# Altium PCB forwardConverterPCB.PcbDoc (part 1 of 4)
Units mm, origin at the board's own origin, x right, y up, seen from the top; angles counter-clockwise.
Board outline 382.81 x 370.12 mm, 8 copper layers (L1, L2 (GND), L3, L4, L5(GND), L6, L7 (GND), L8), stack 1.028 mm thick; 352 components, 187 nets, 1188 pads, 1016 vias.
Unrouted connection lines stored in the file: 19.
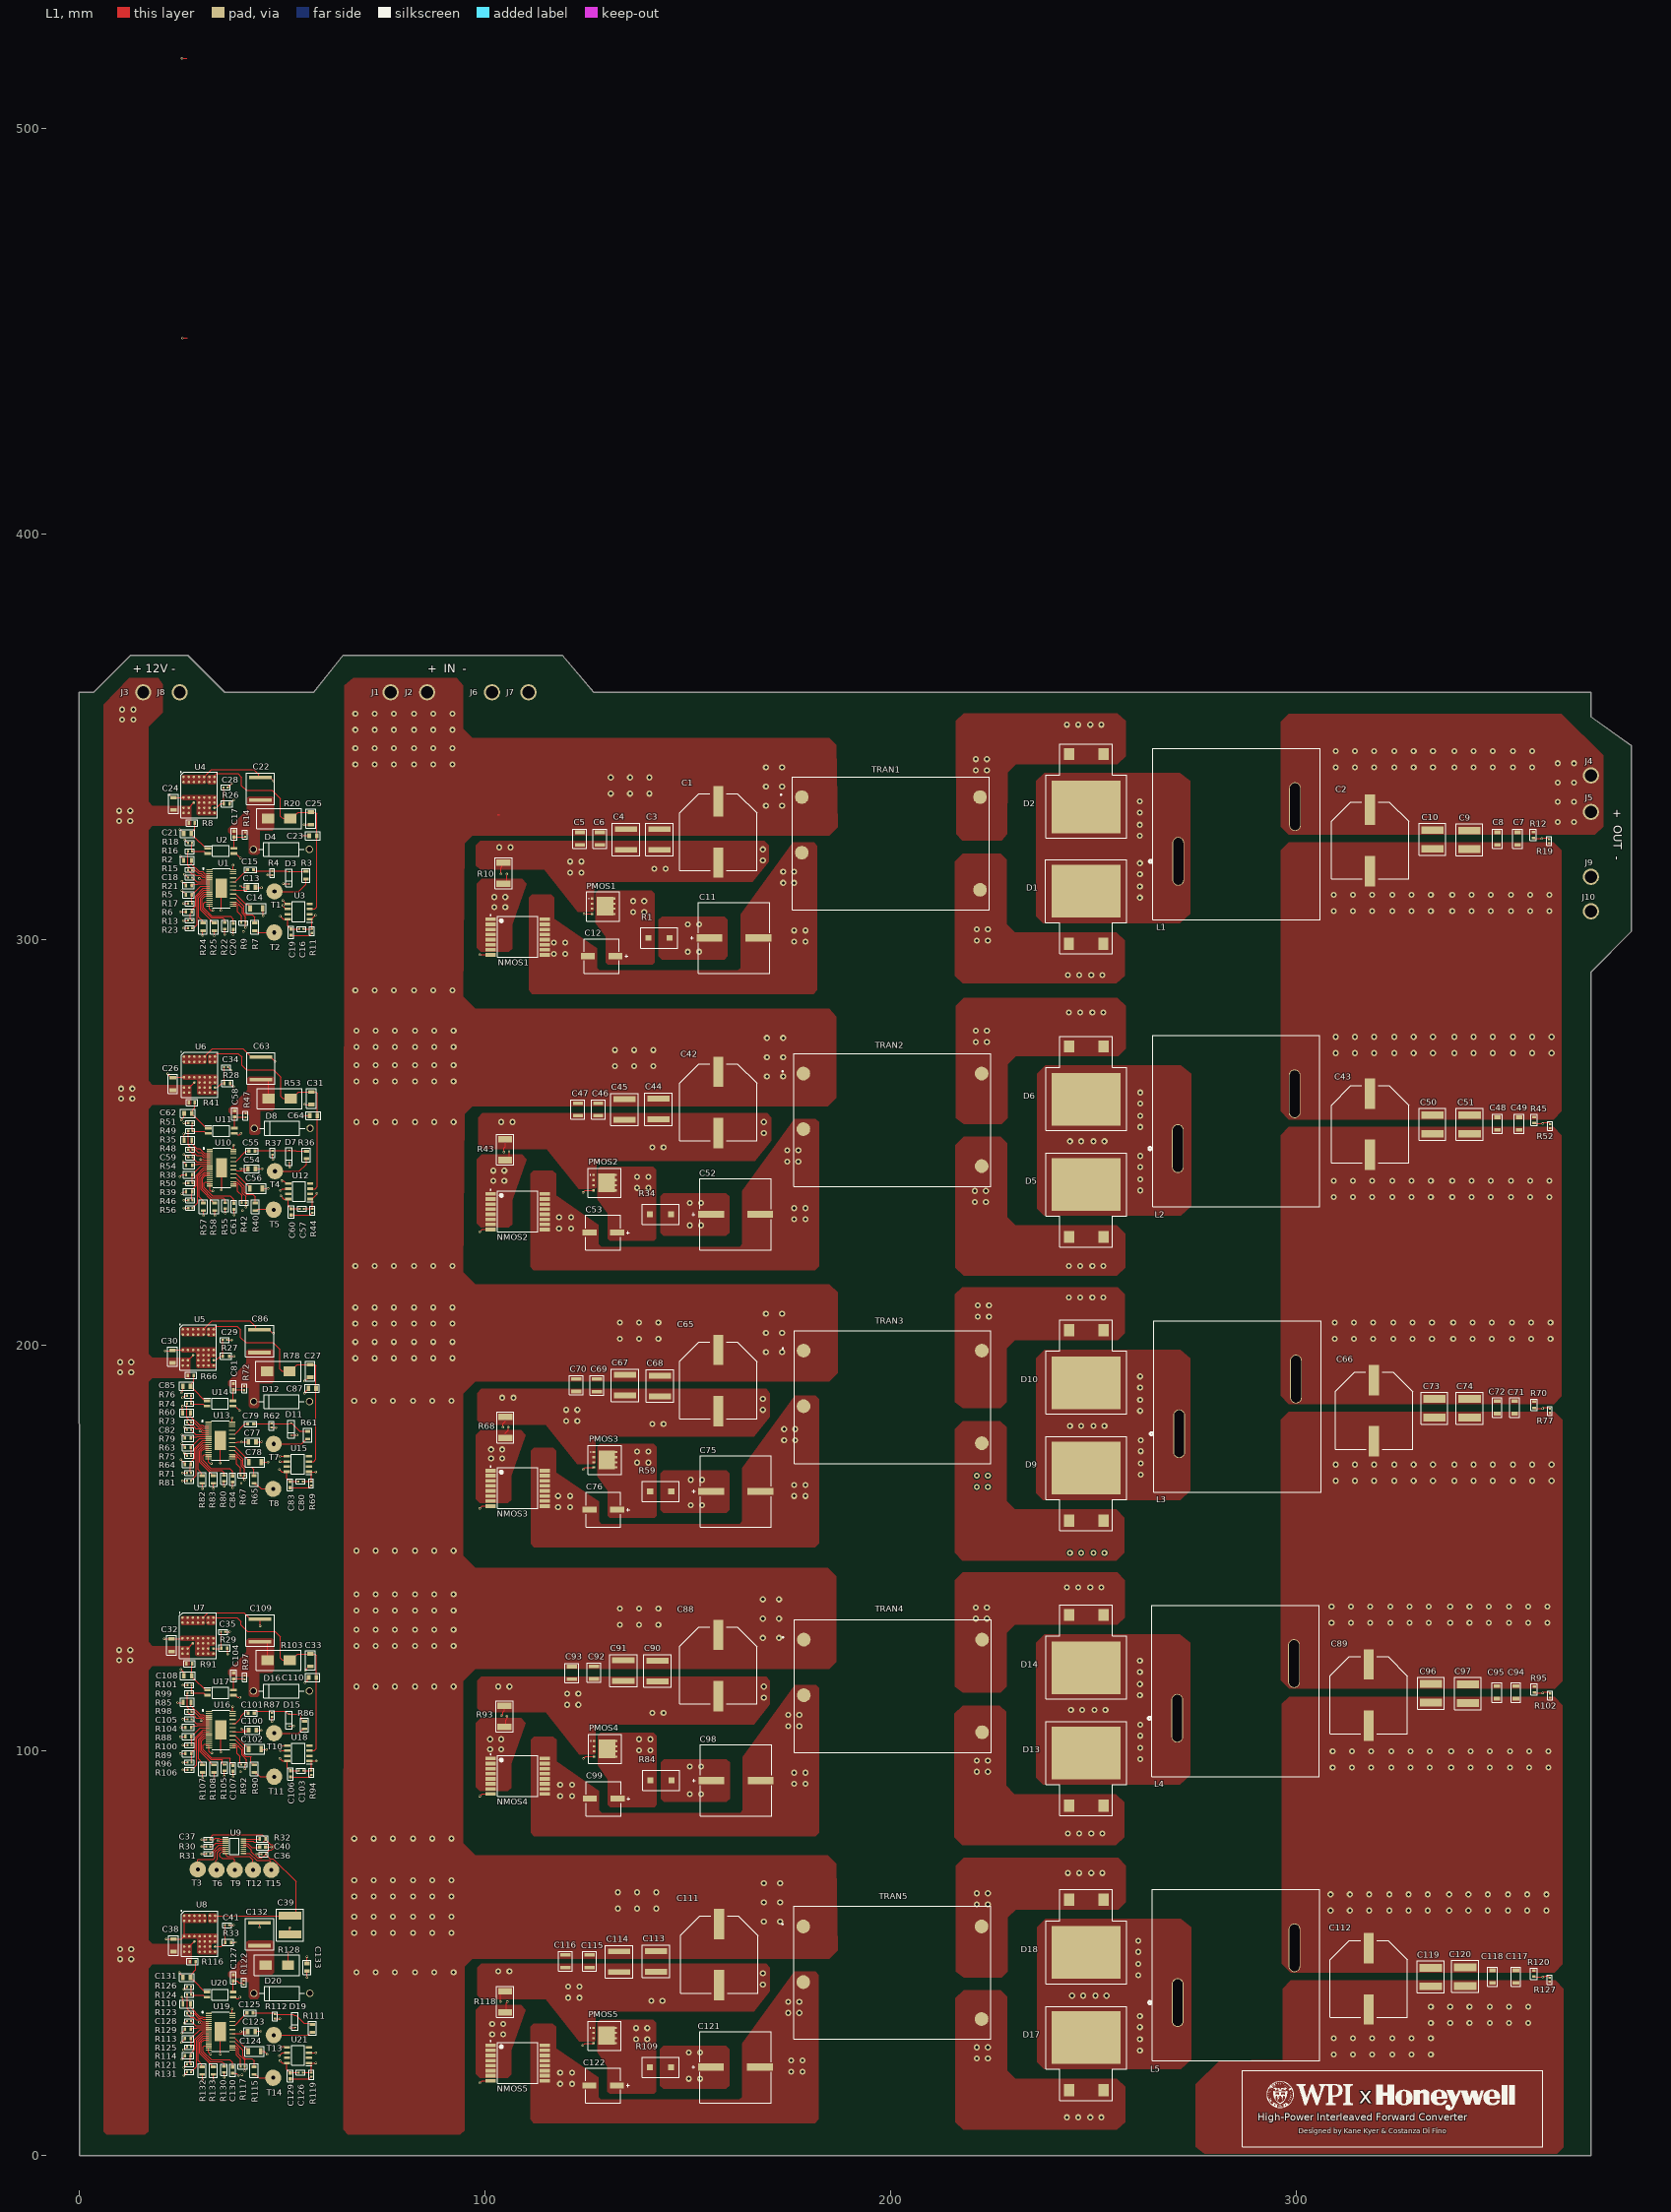
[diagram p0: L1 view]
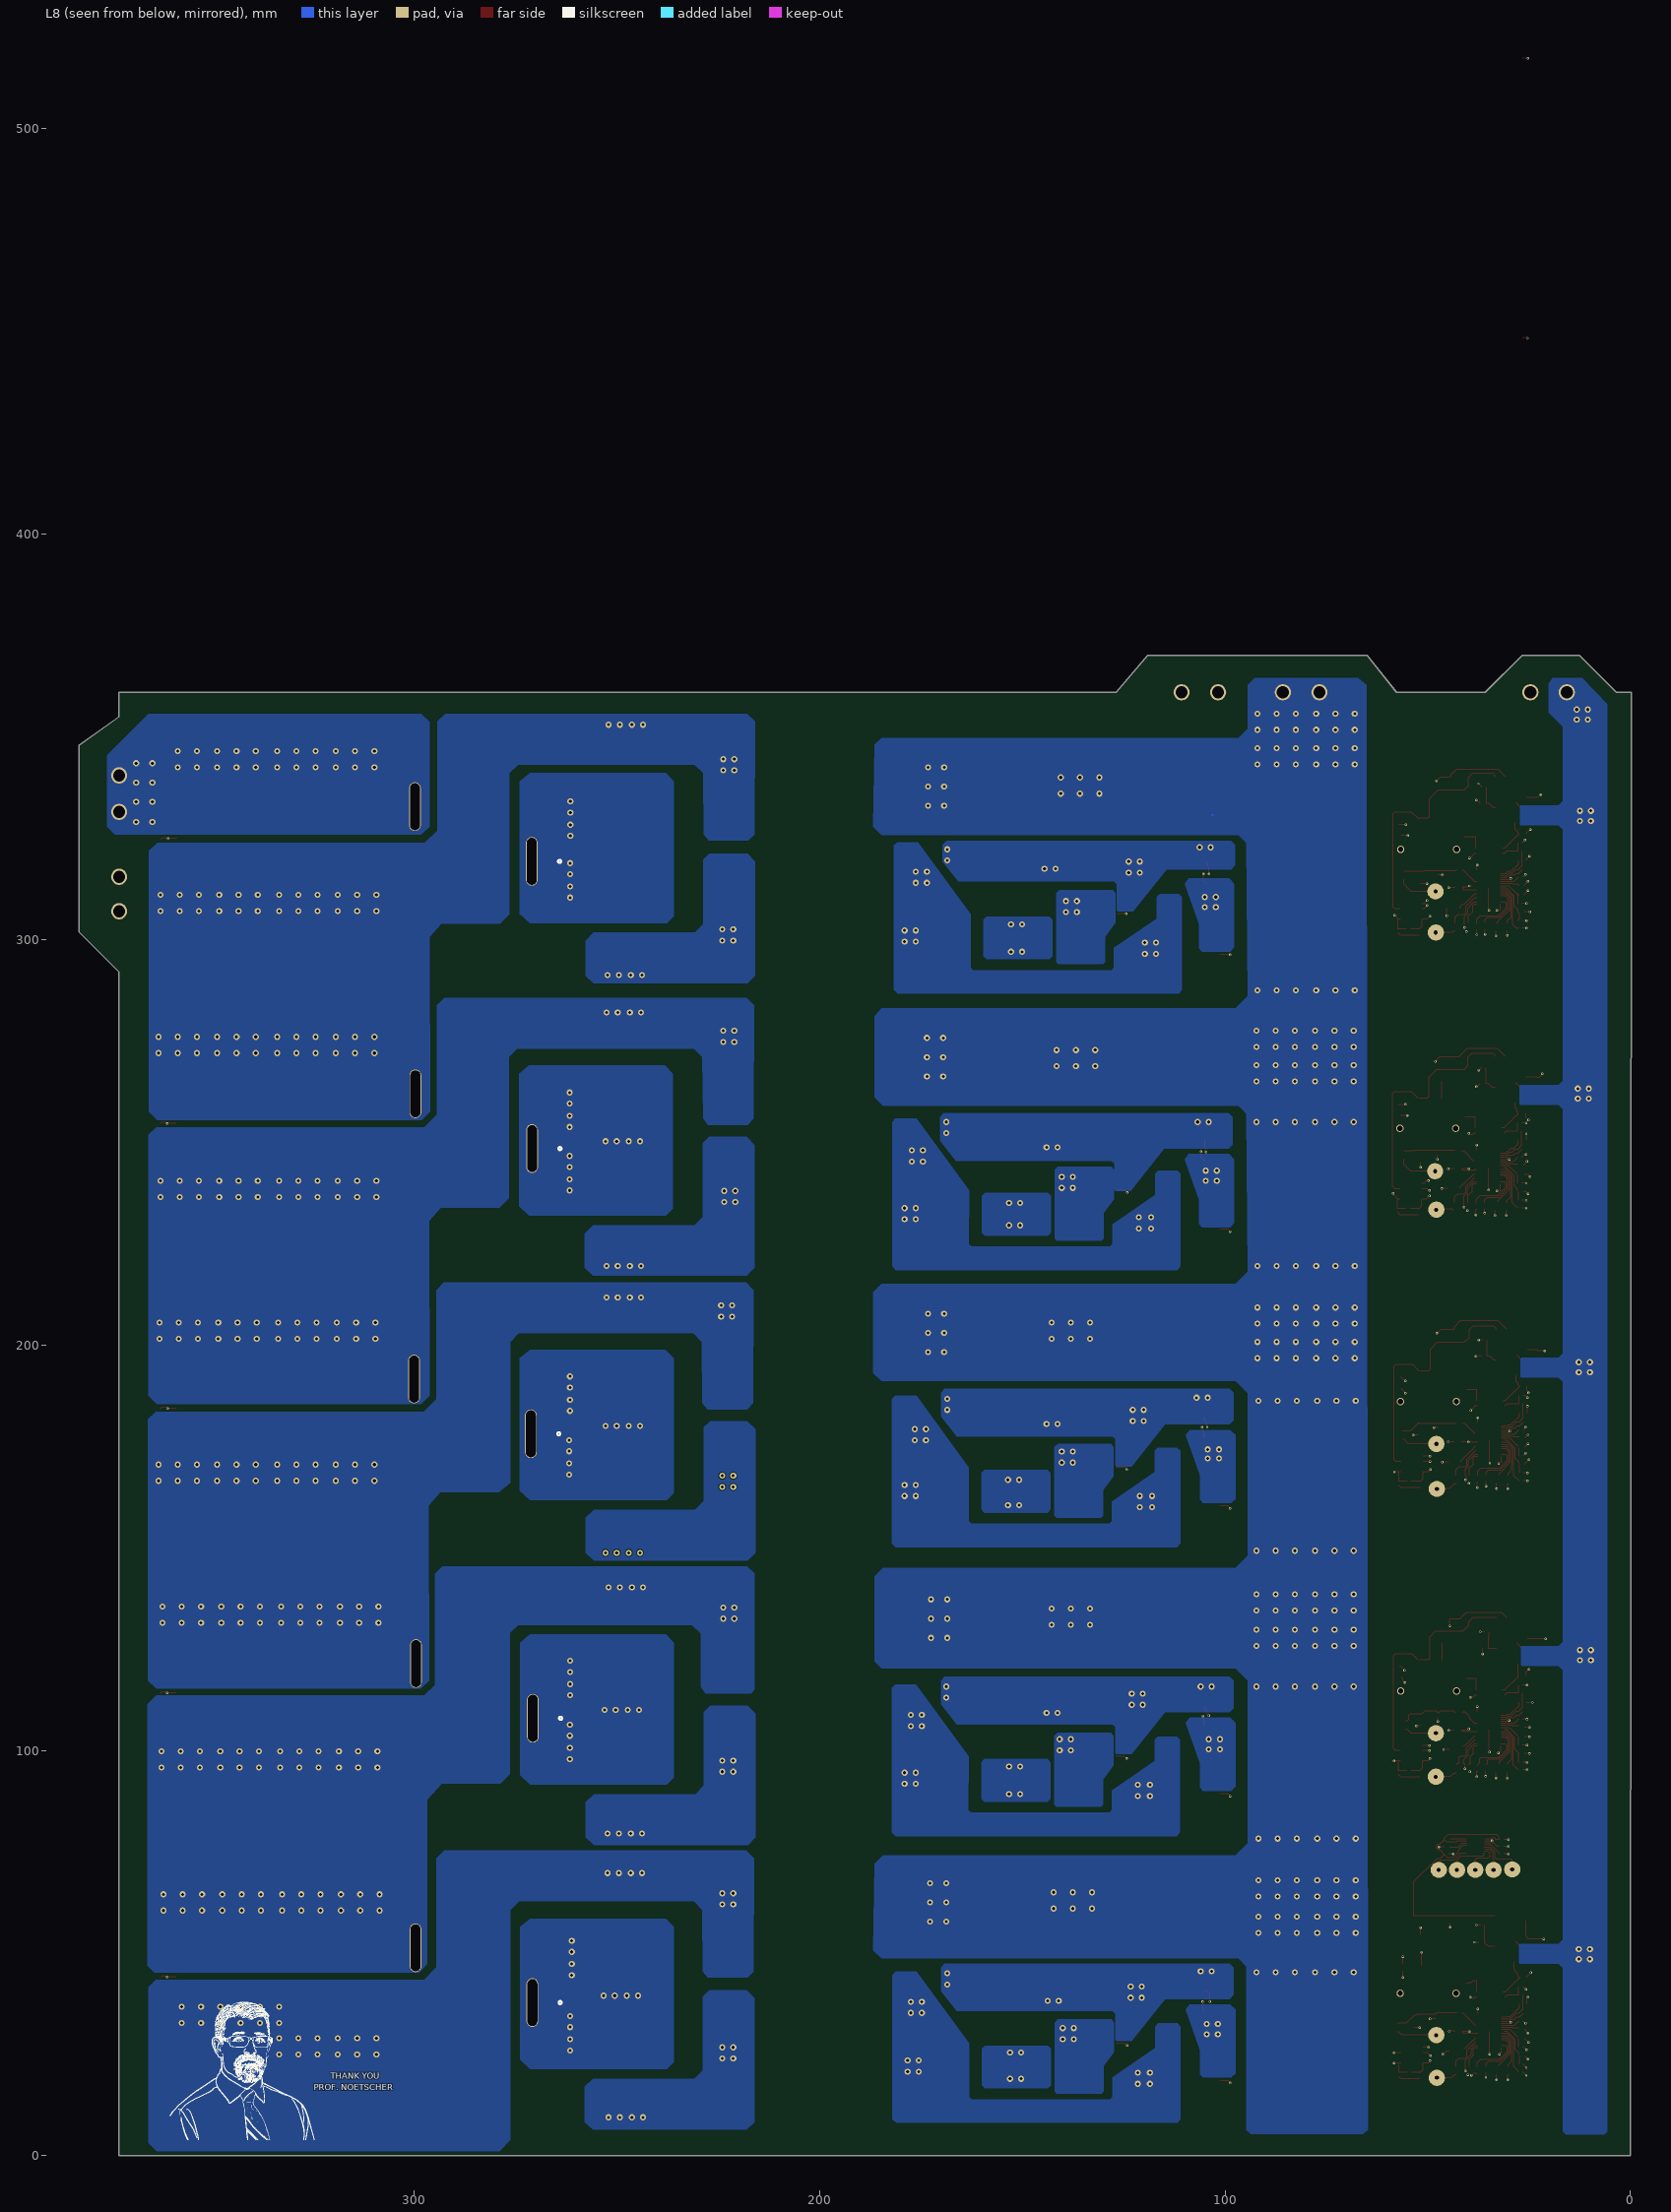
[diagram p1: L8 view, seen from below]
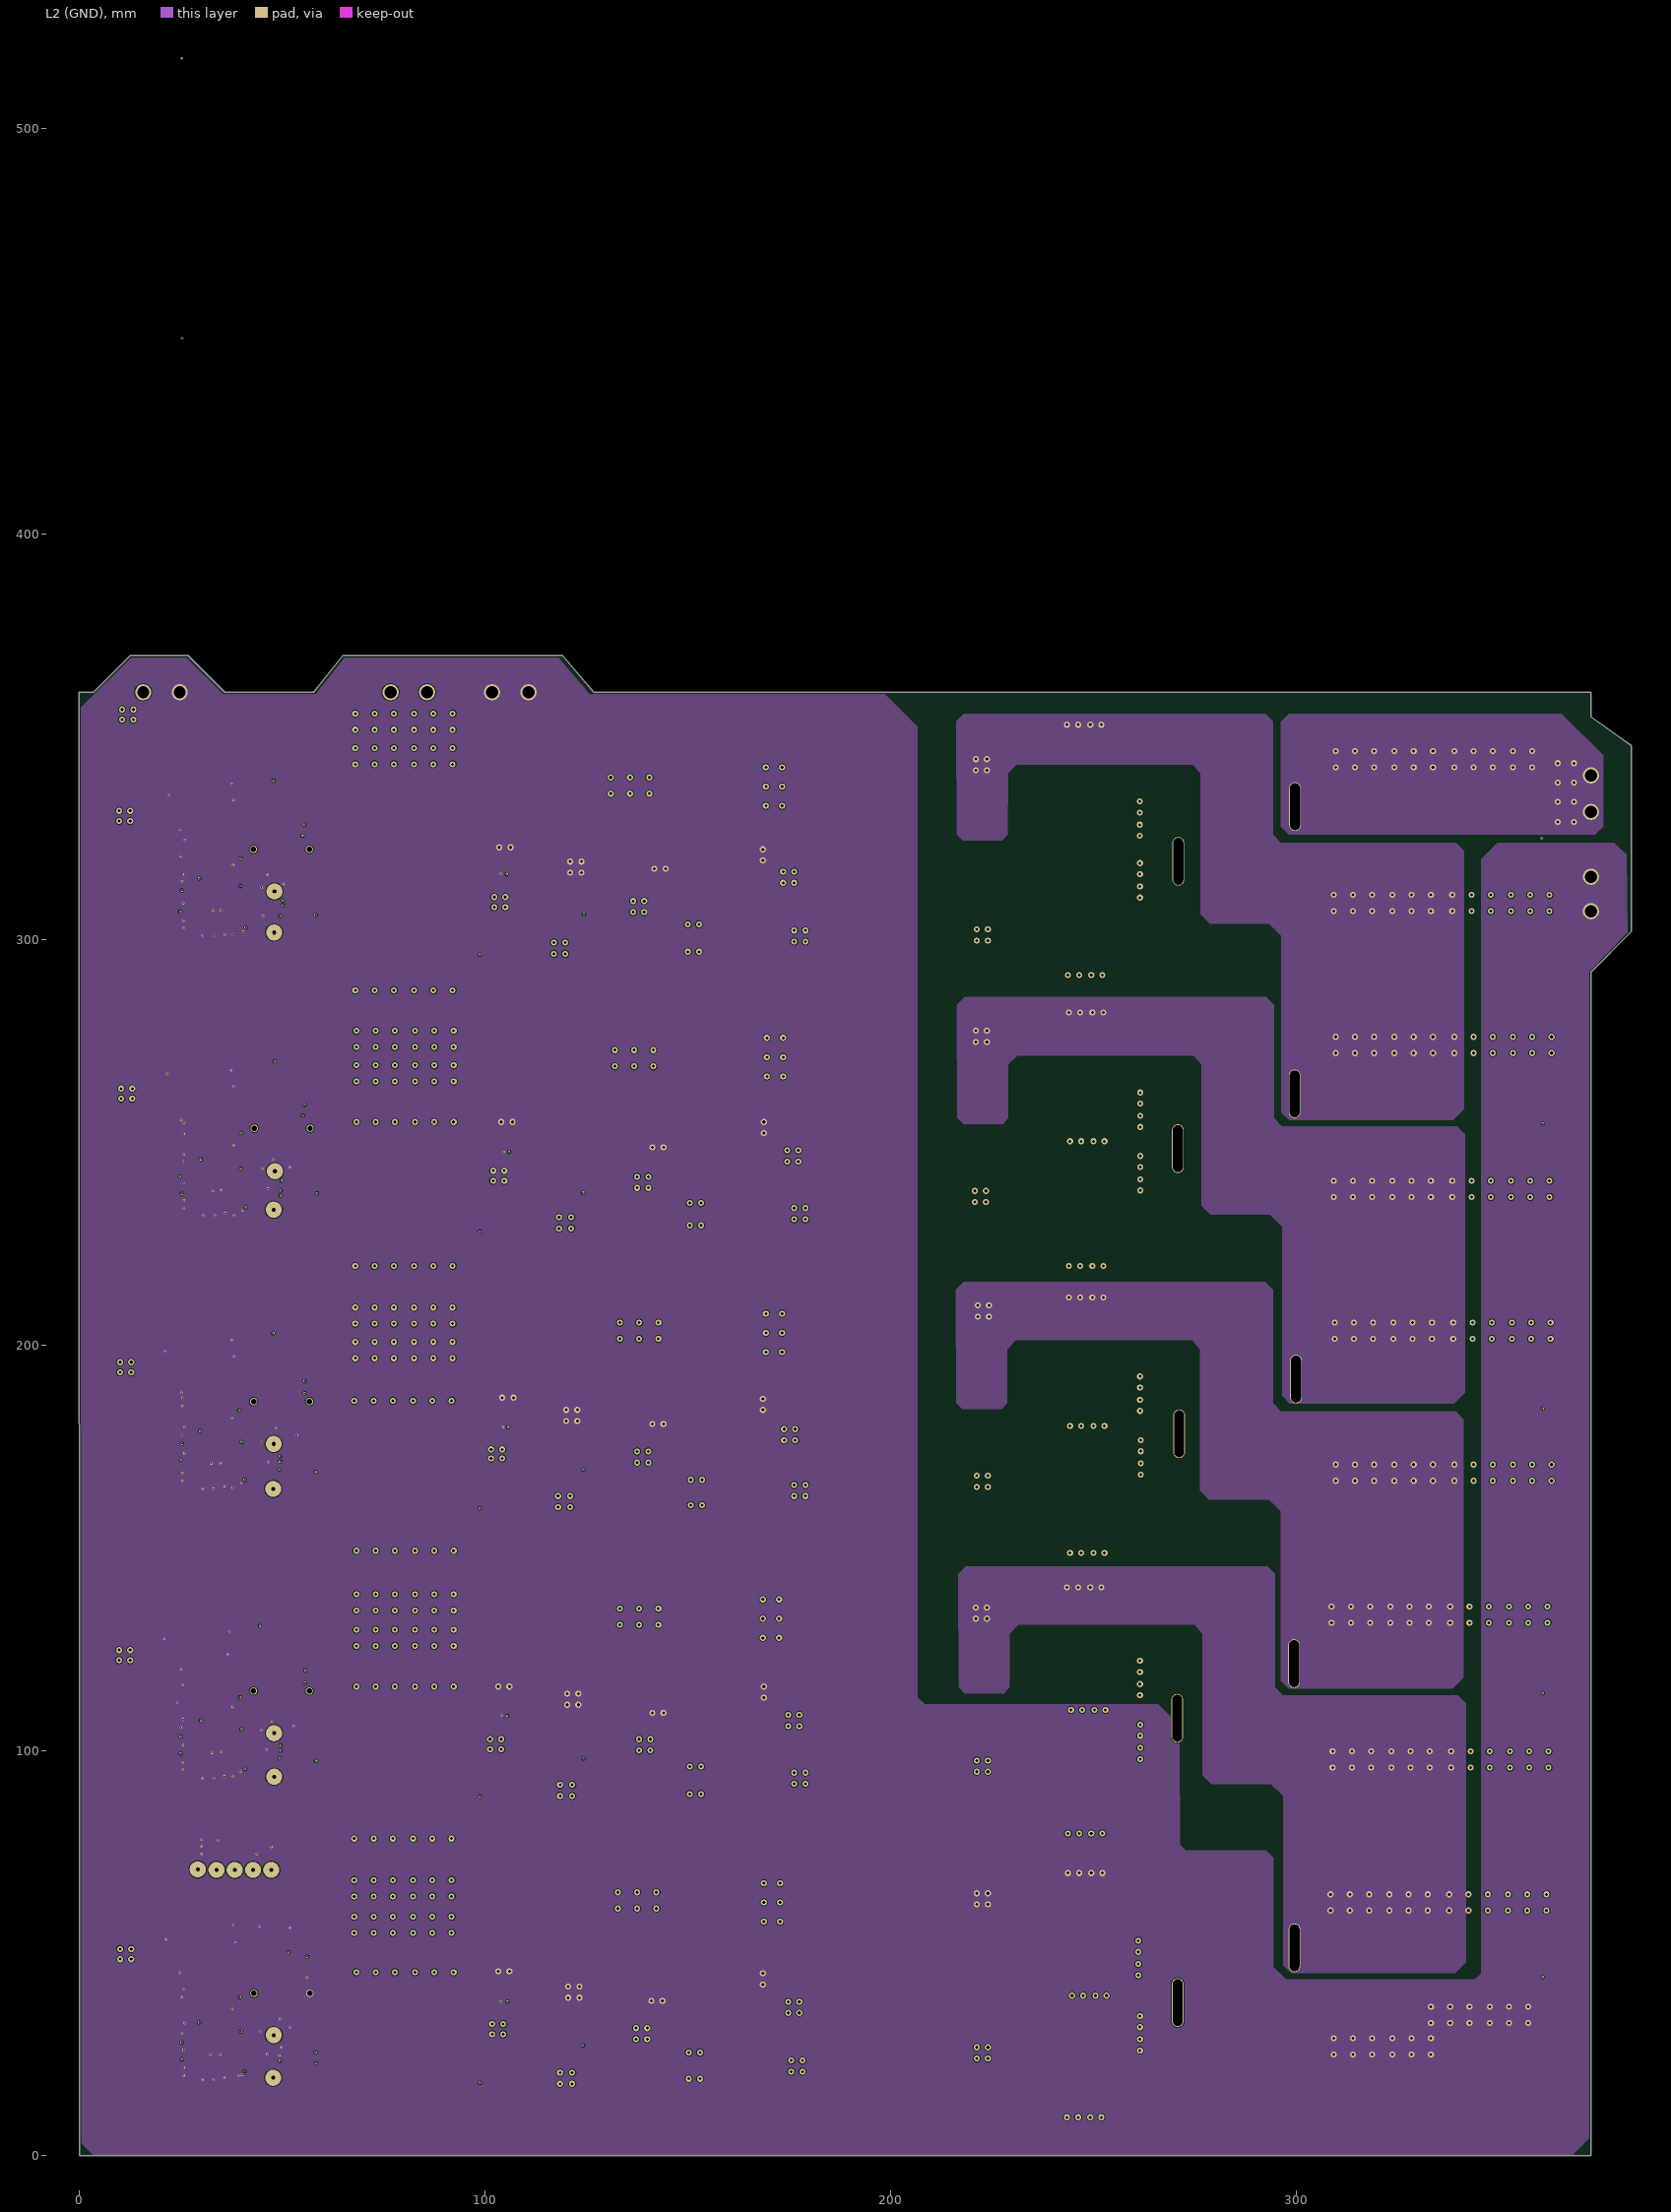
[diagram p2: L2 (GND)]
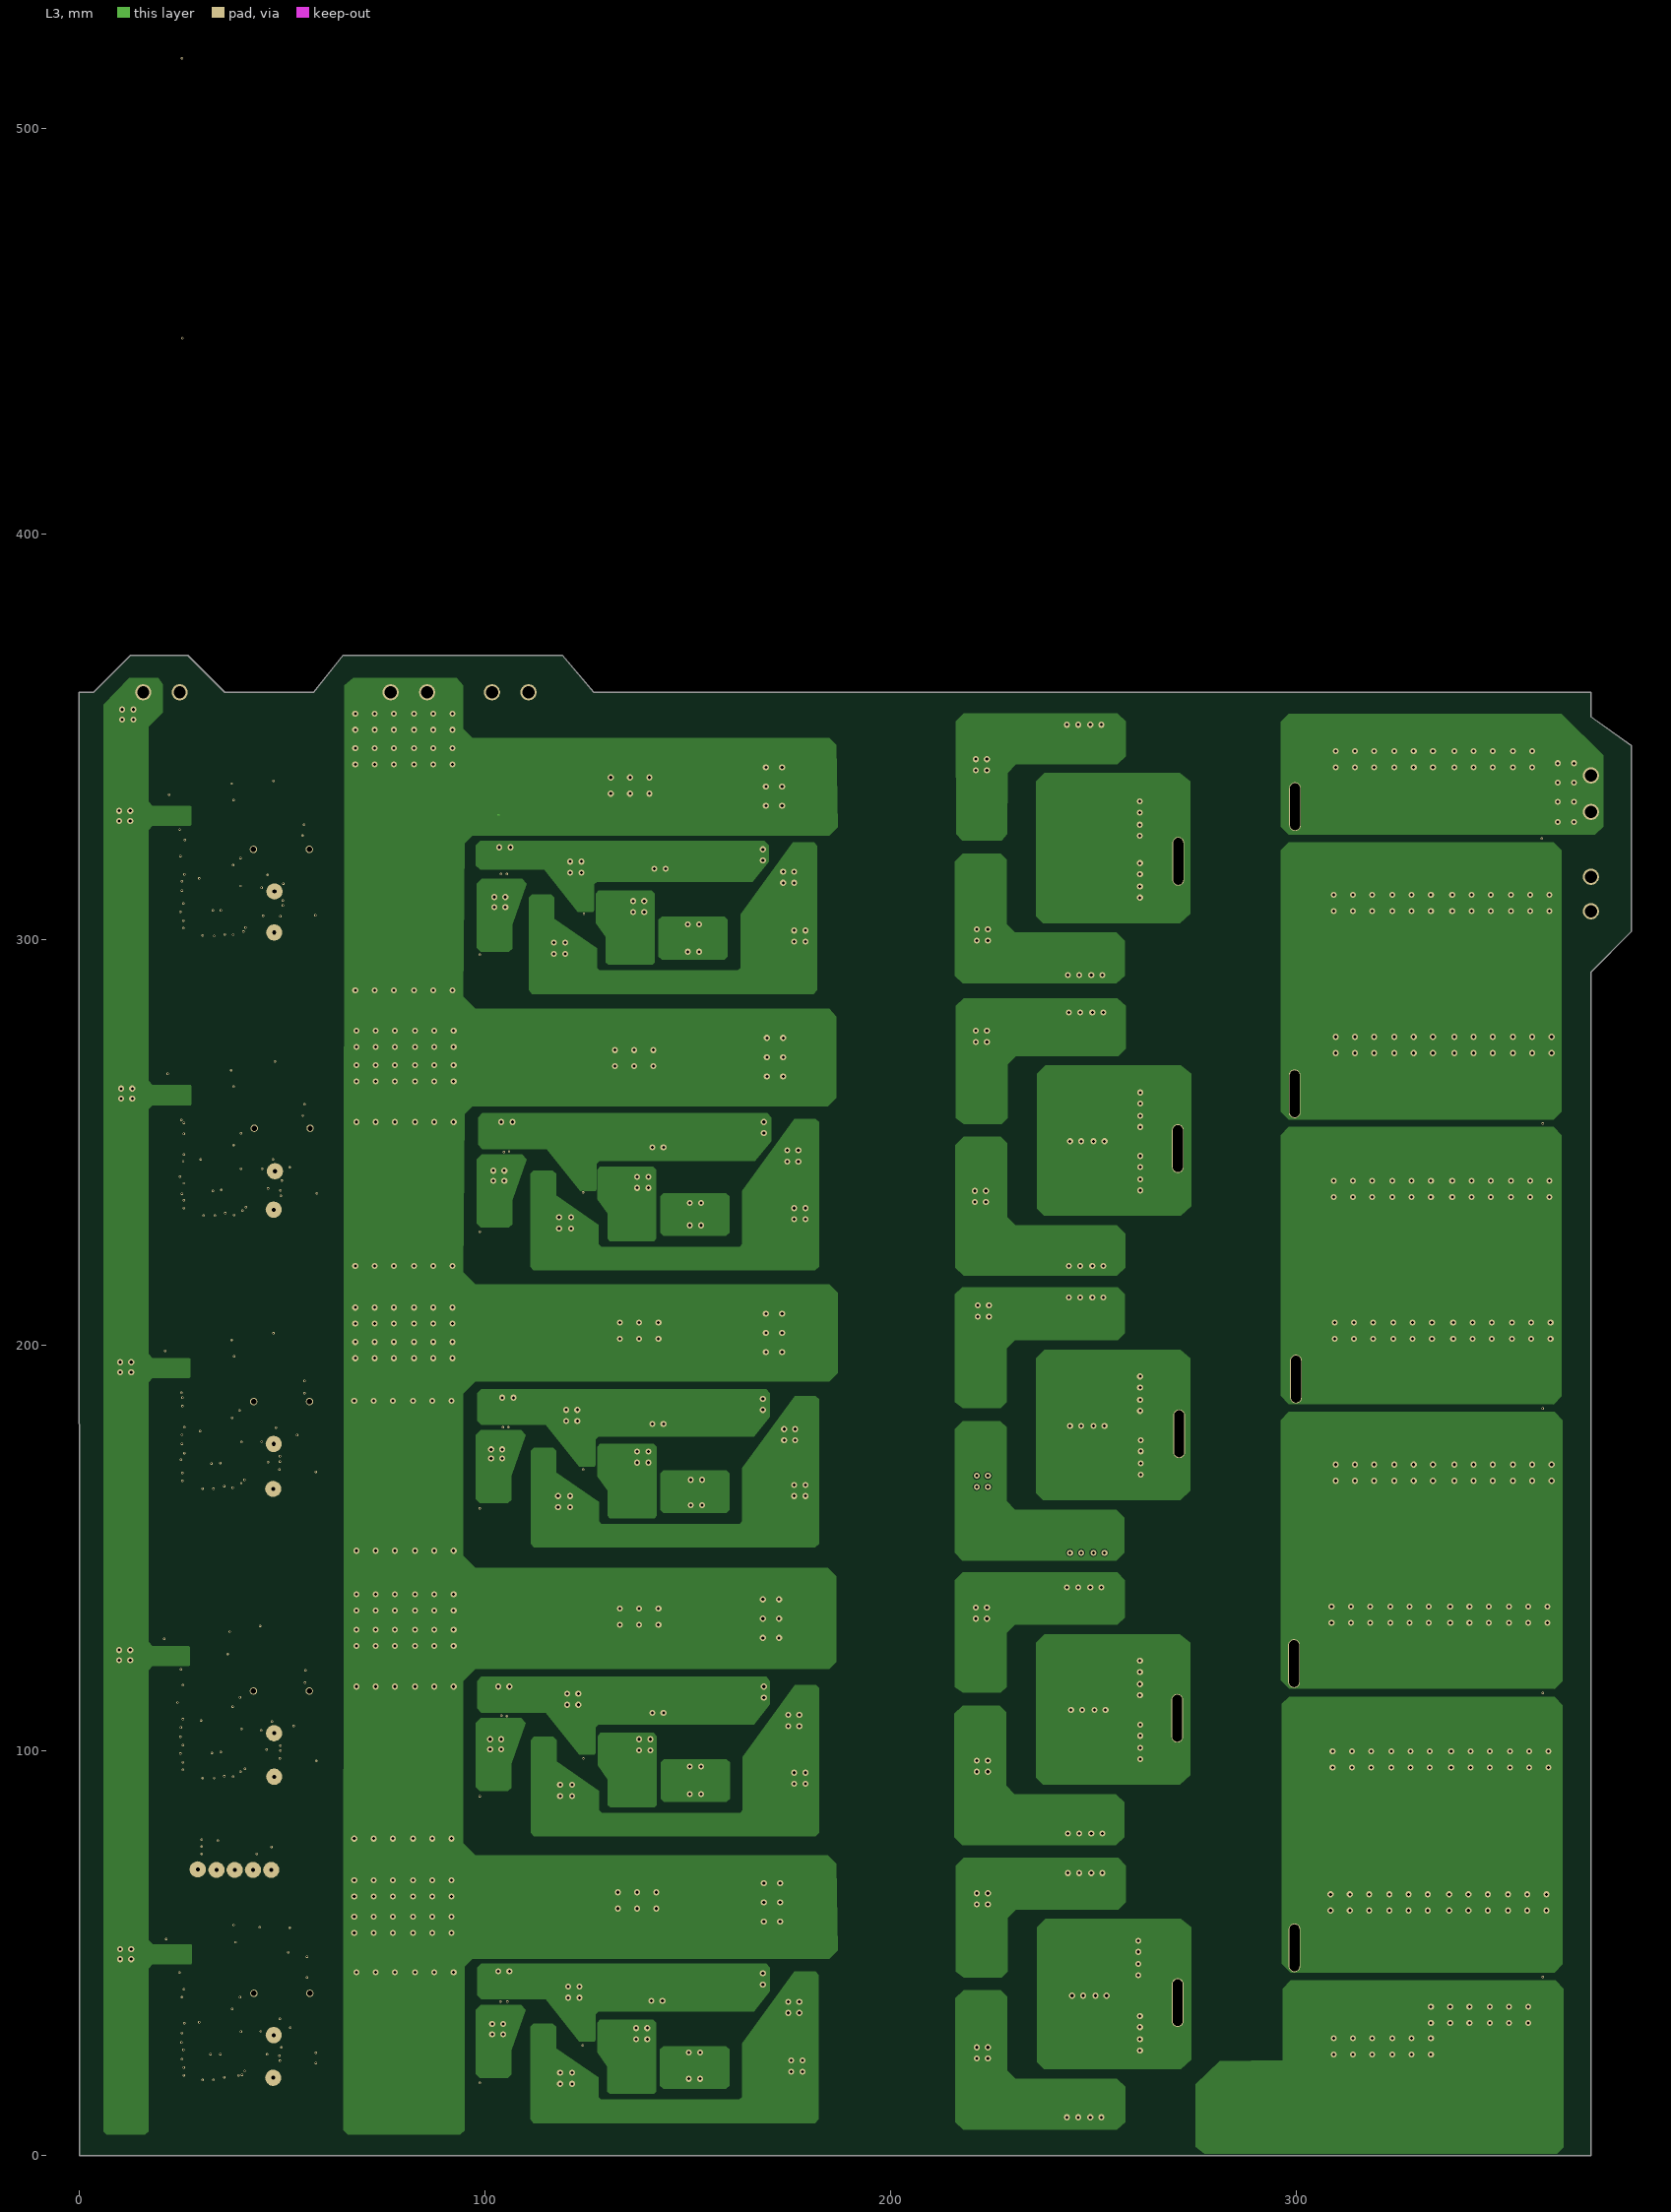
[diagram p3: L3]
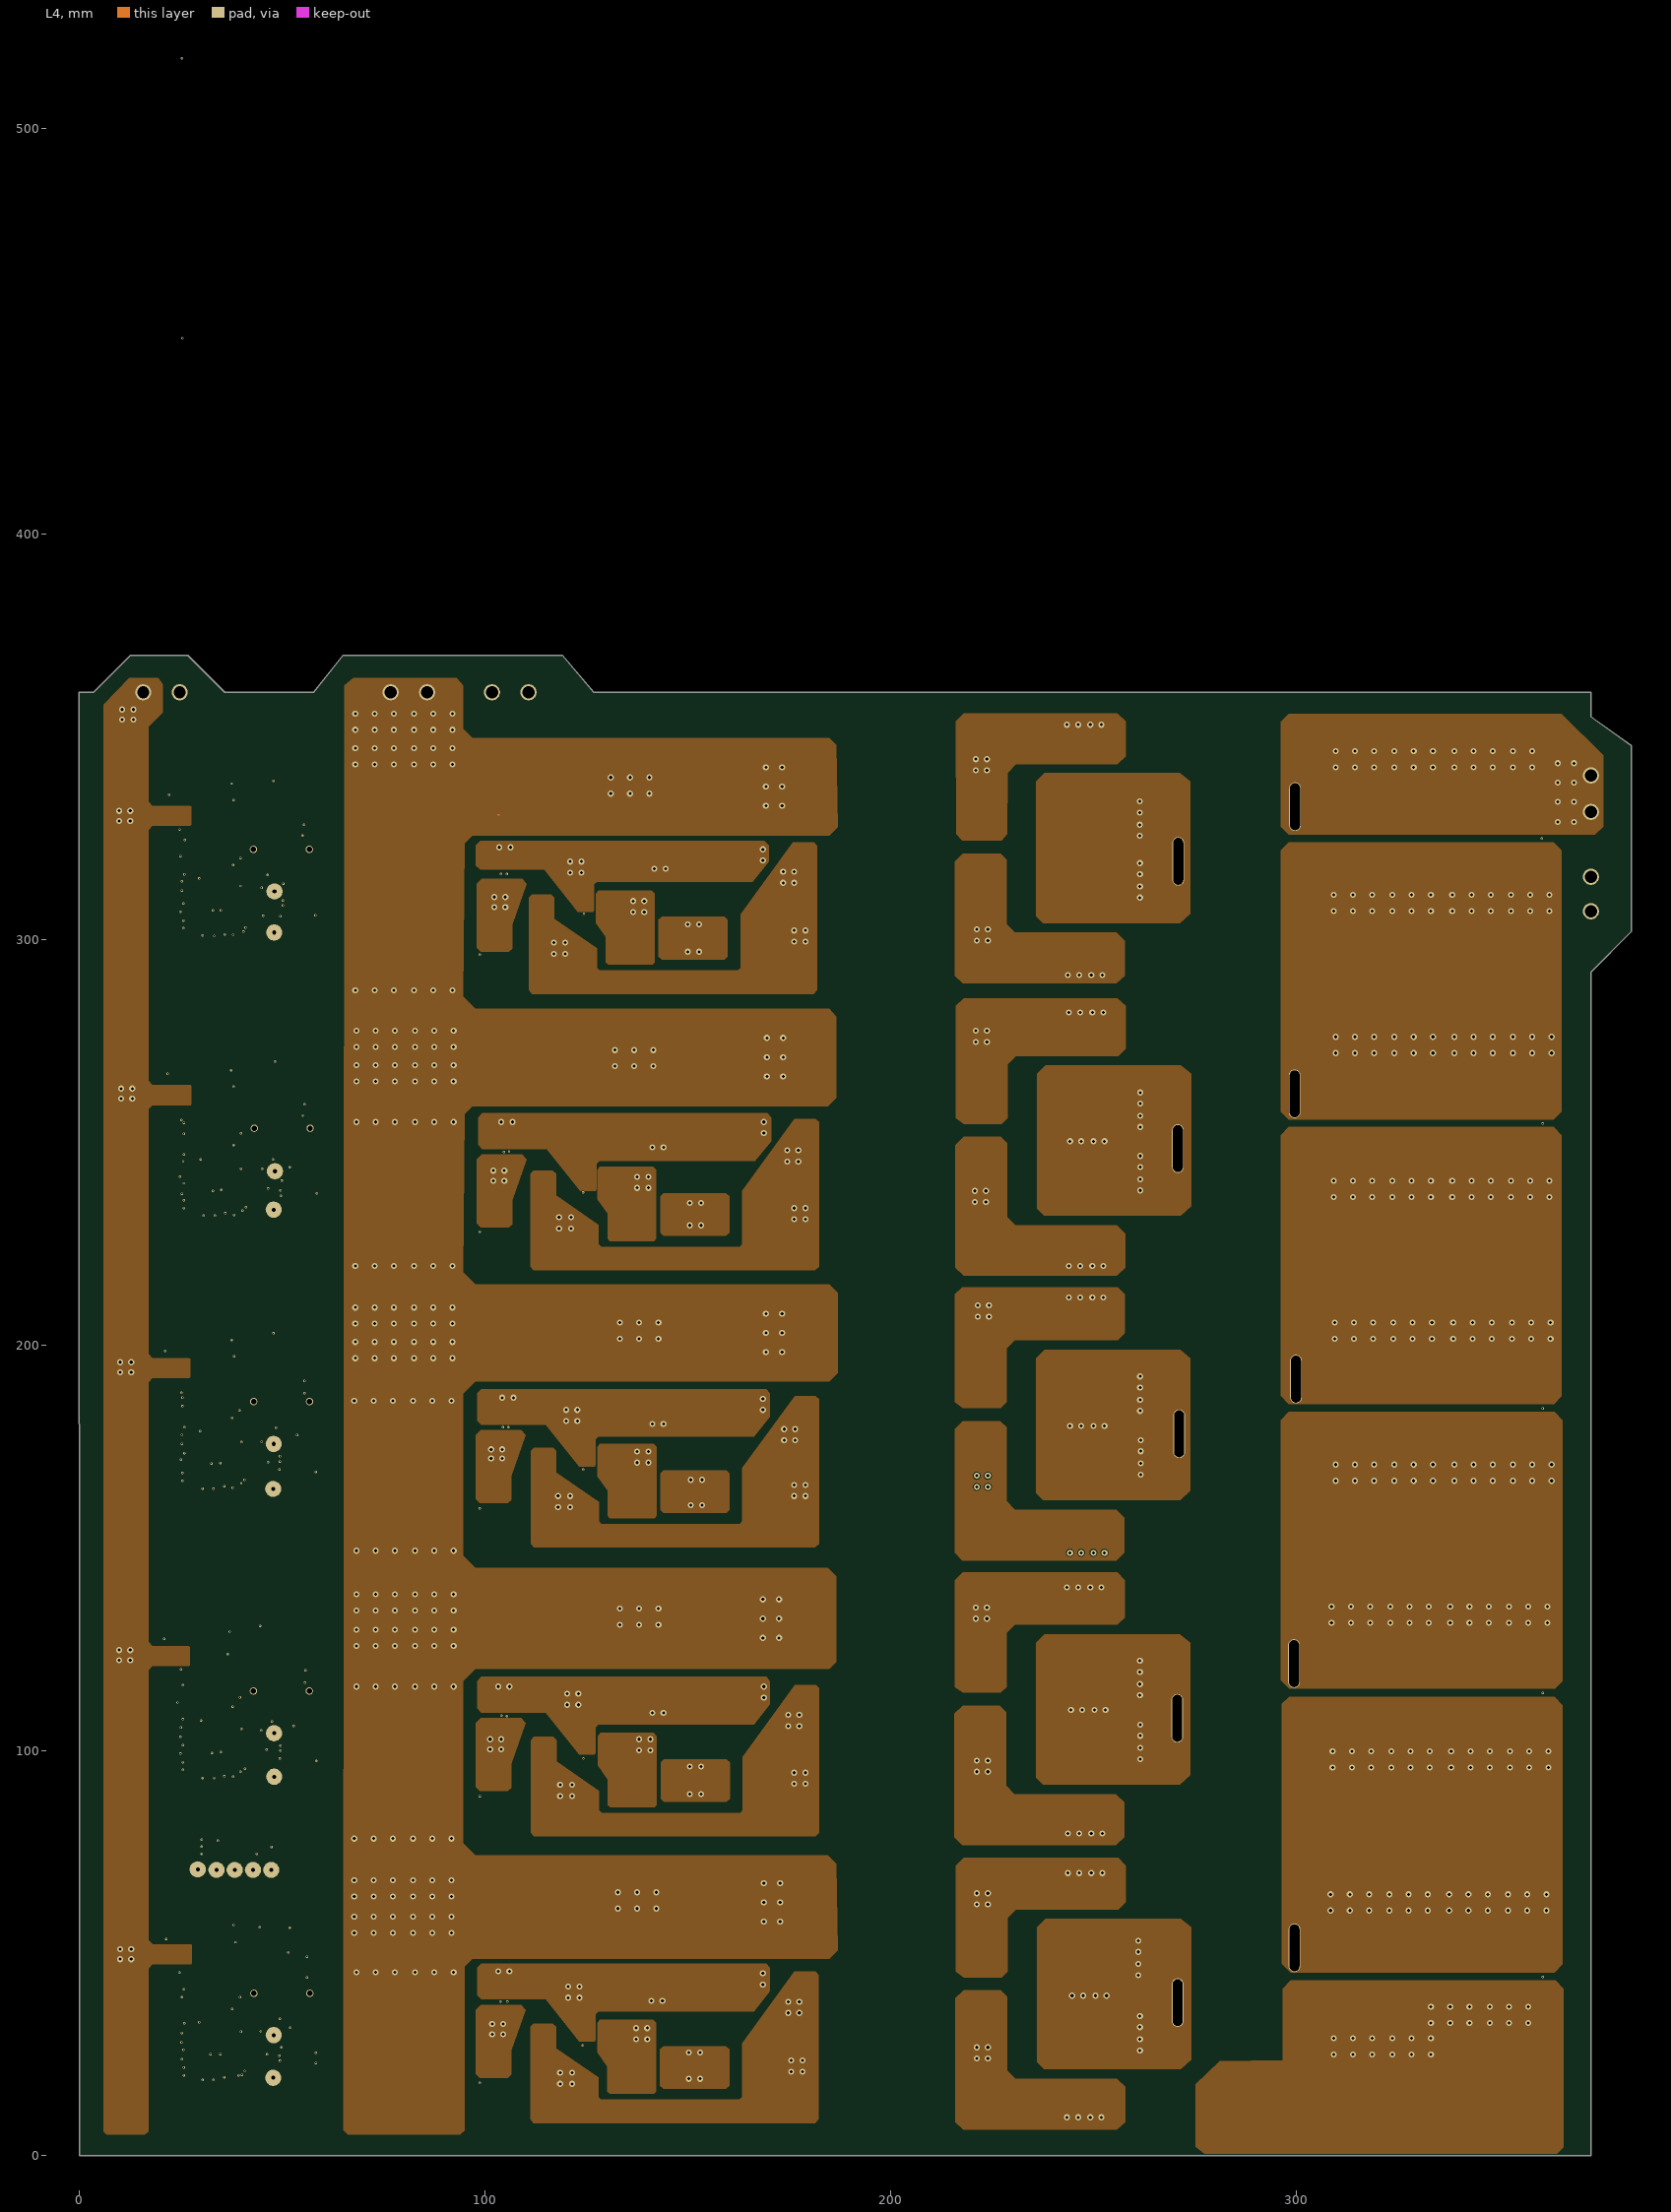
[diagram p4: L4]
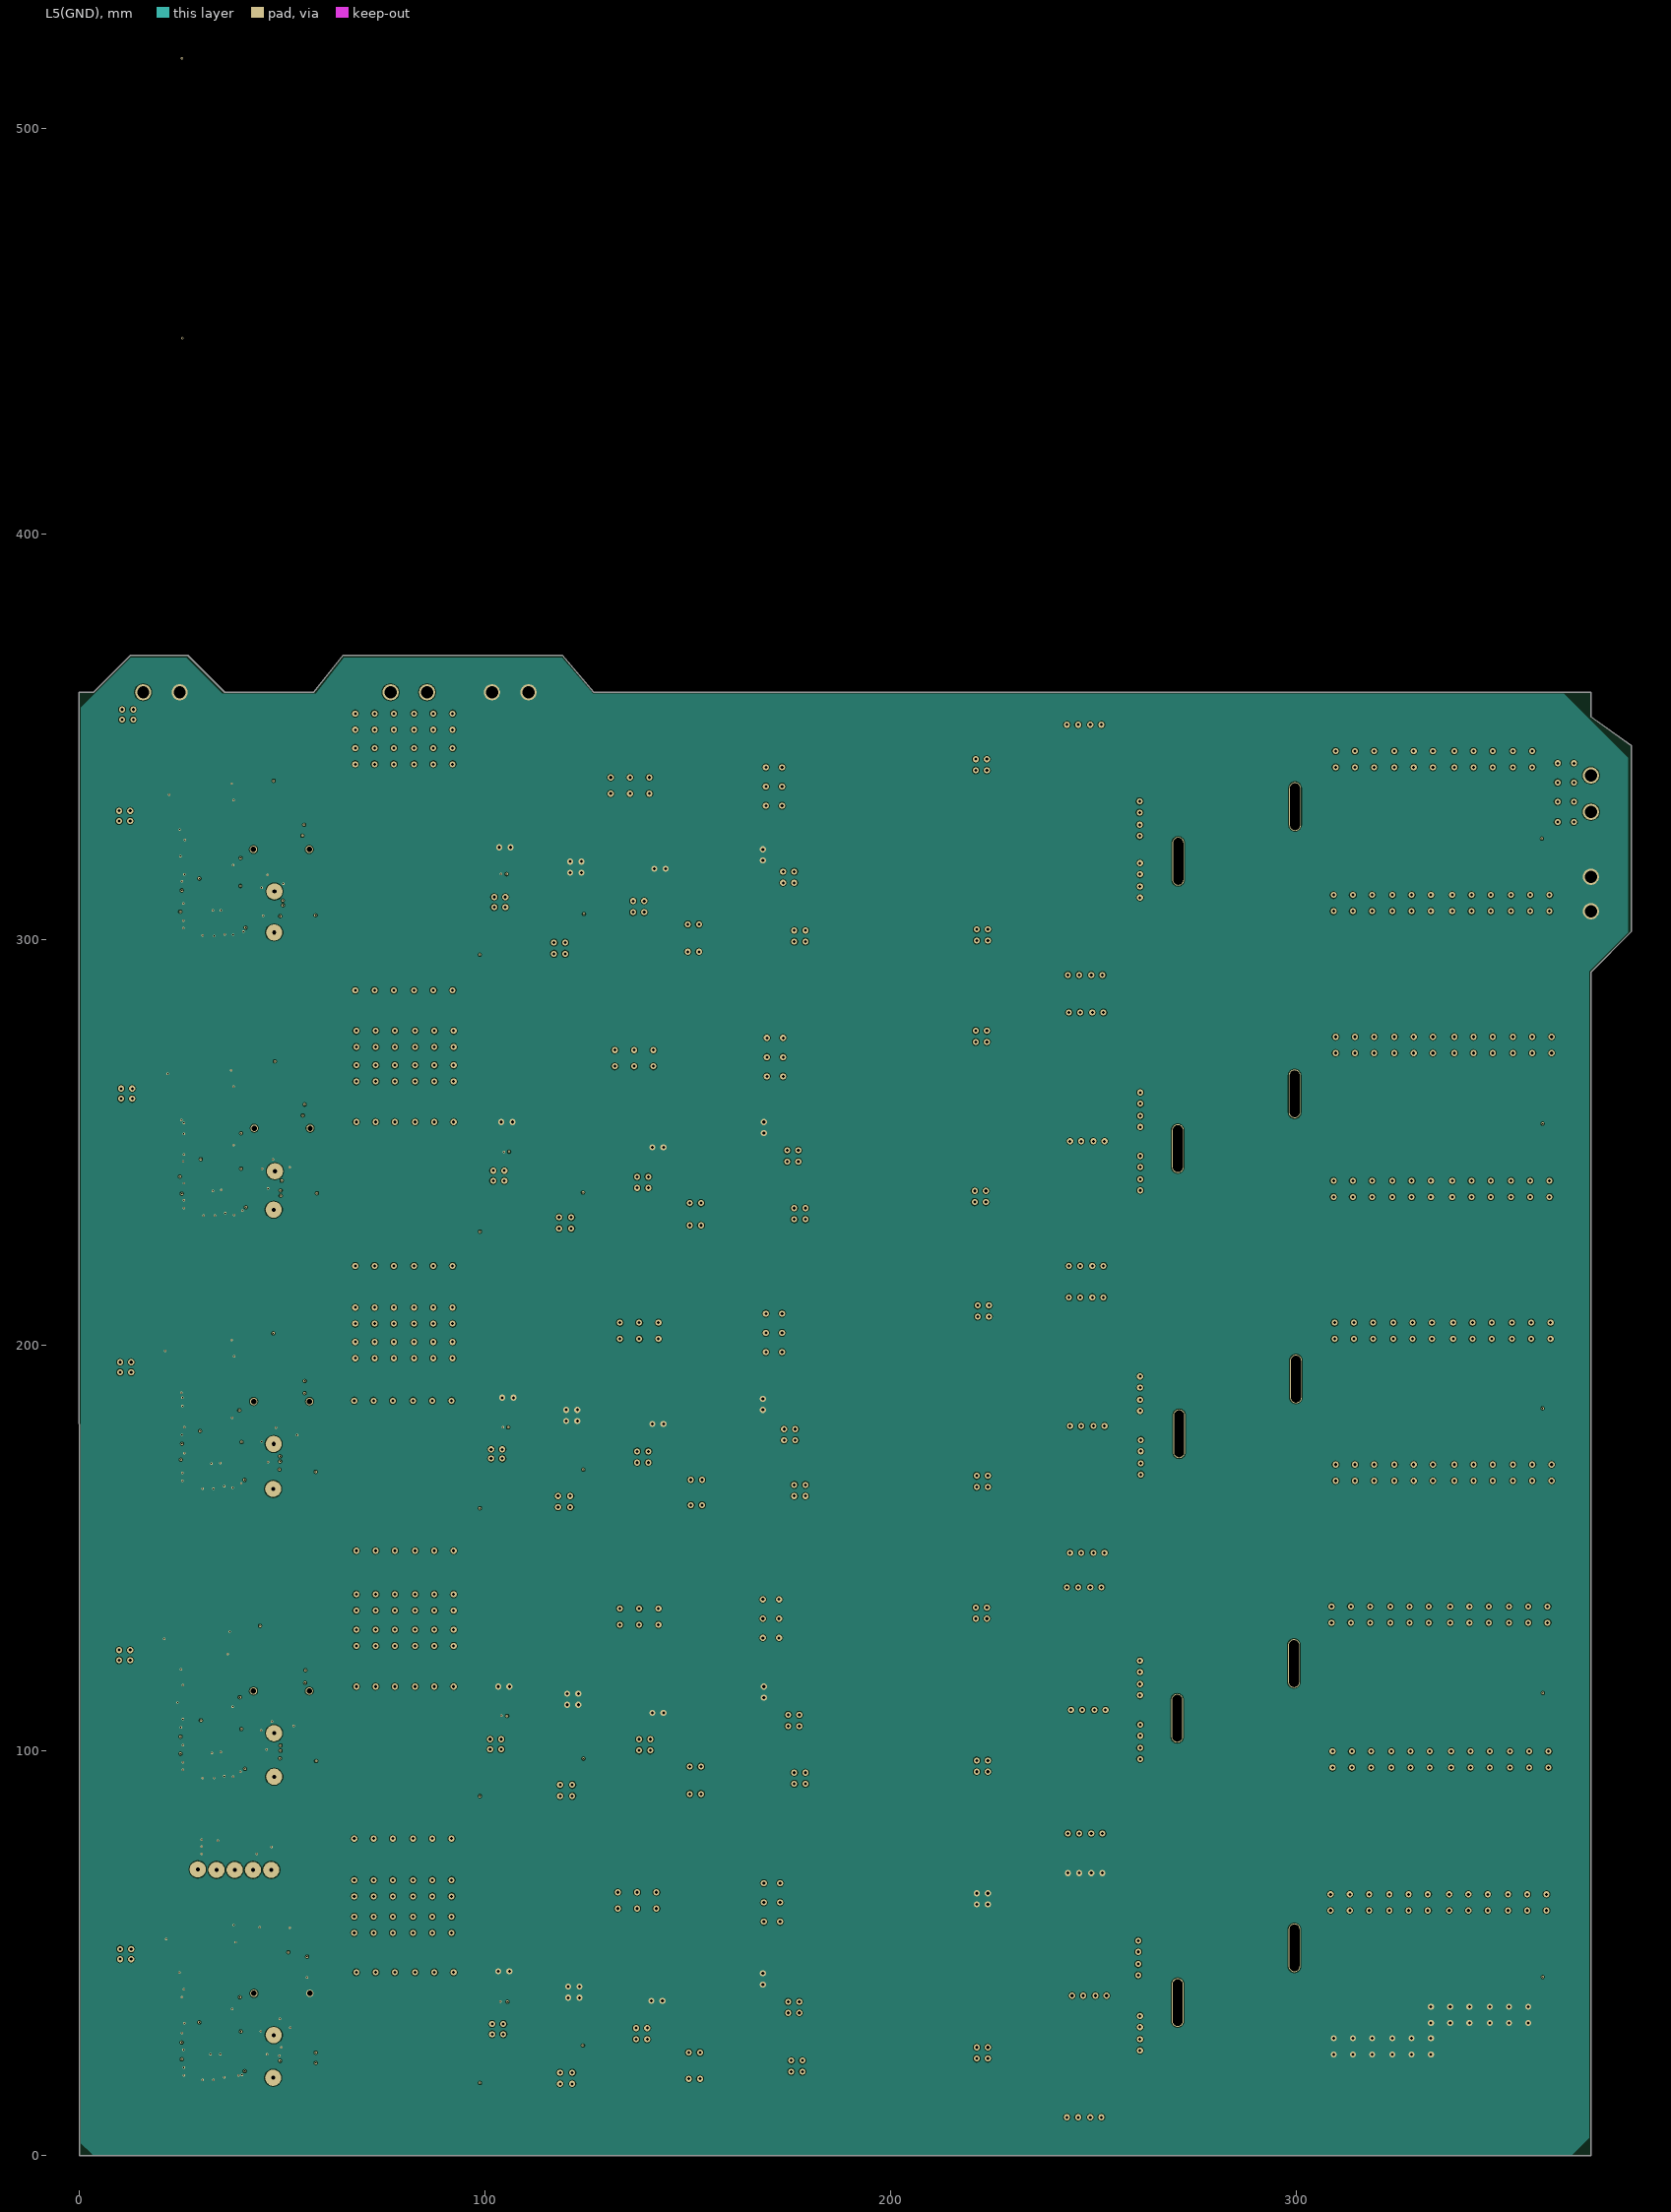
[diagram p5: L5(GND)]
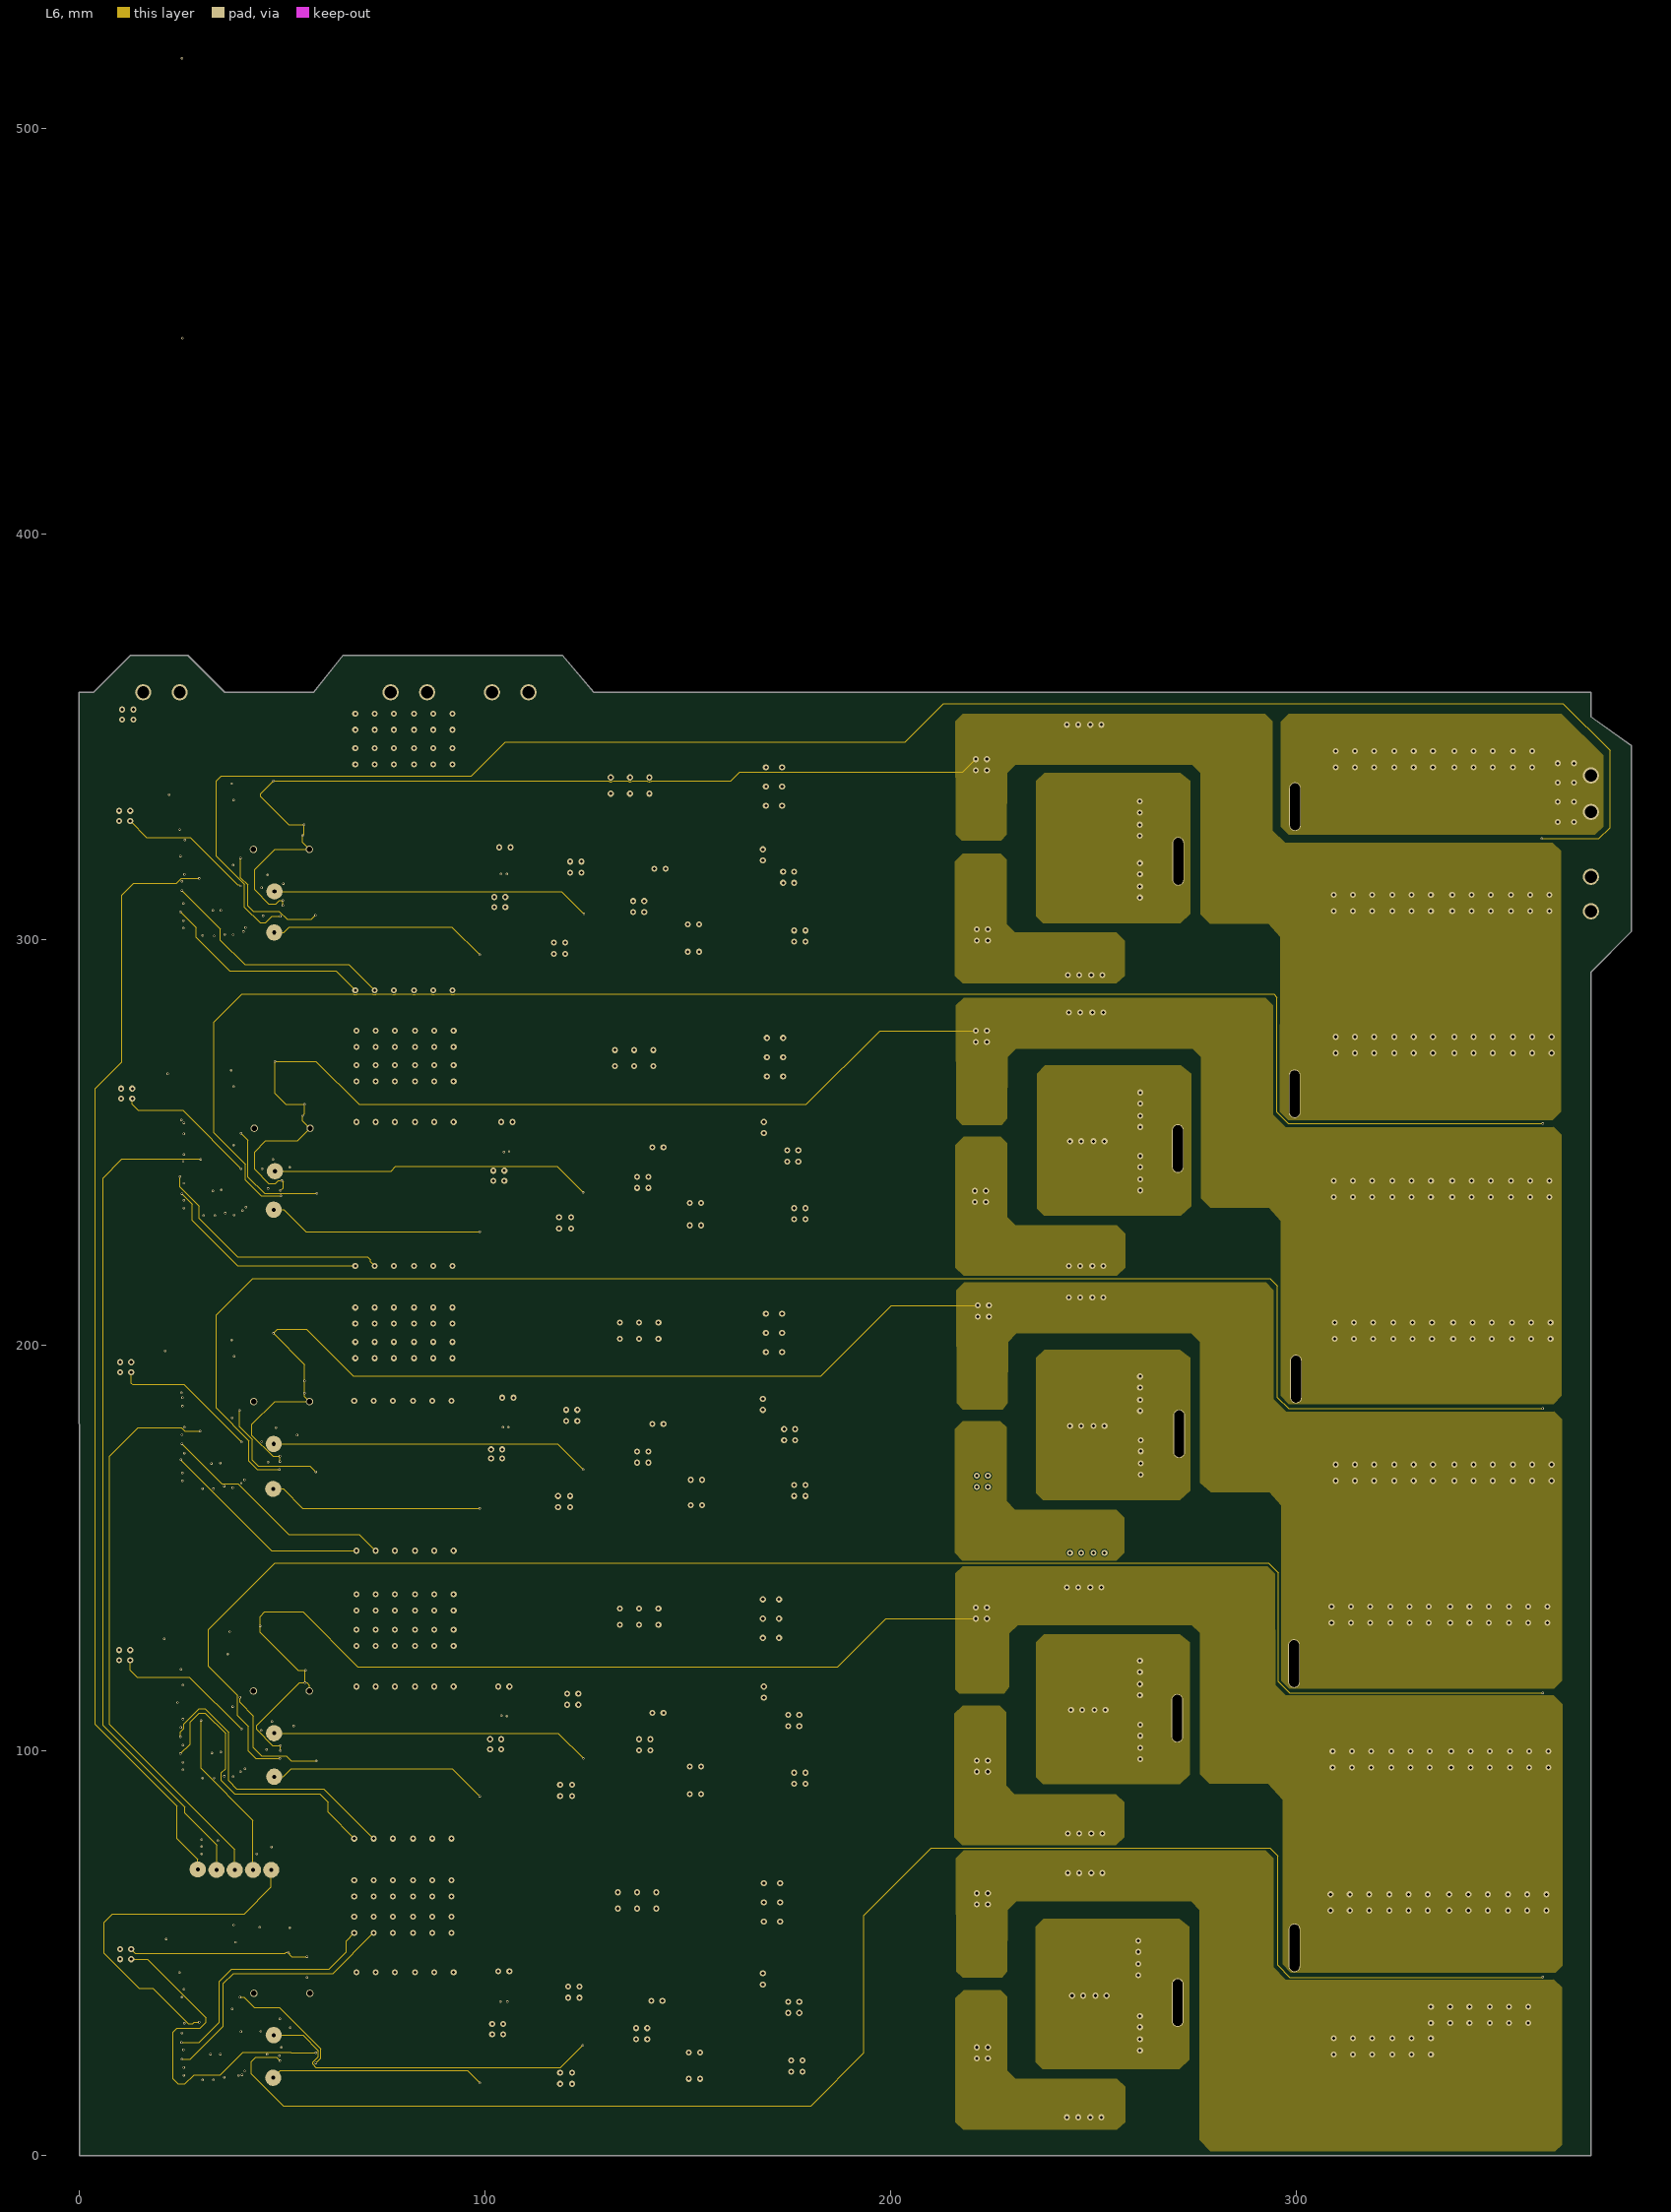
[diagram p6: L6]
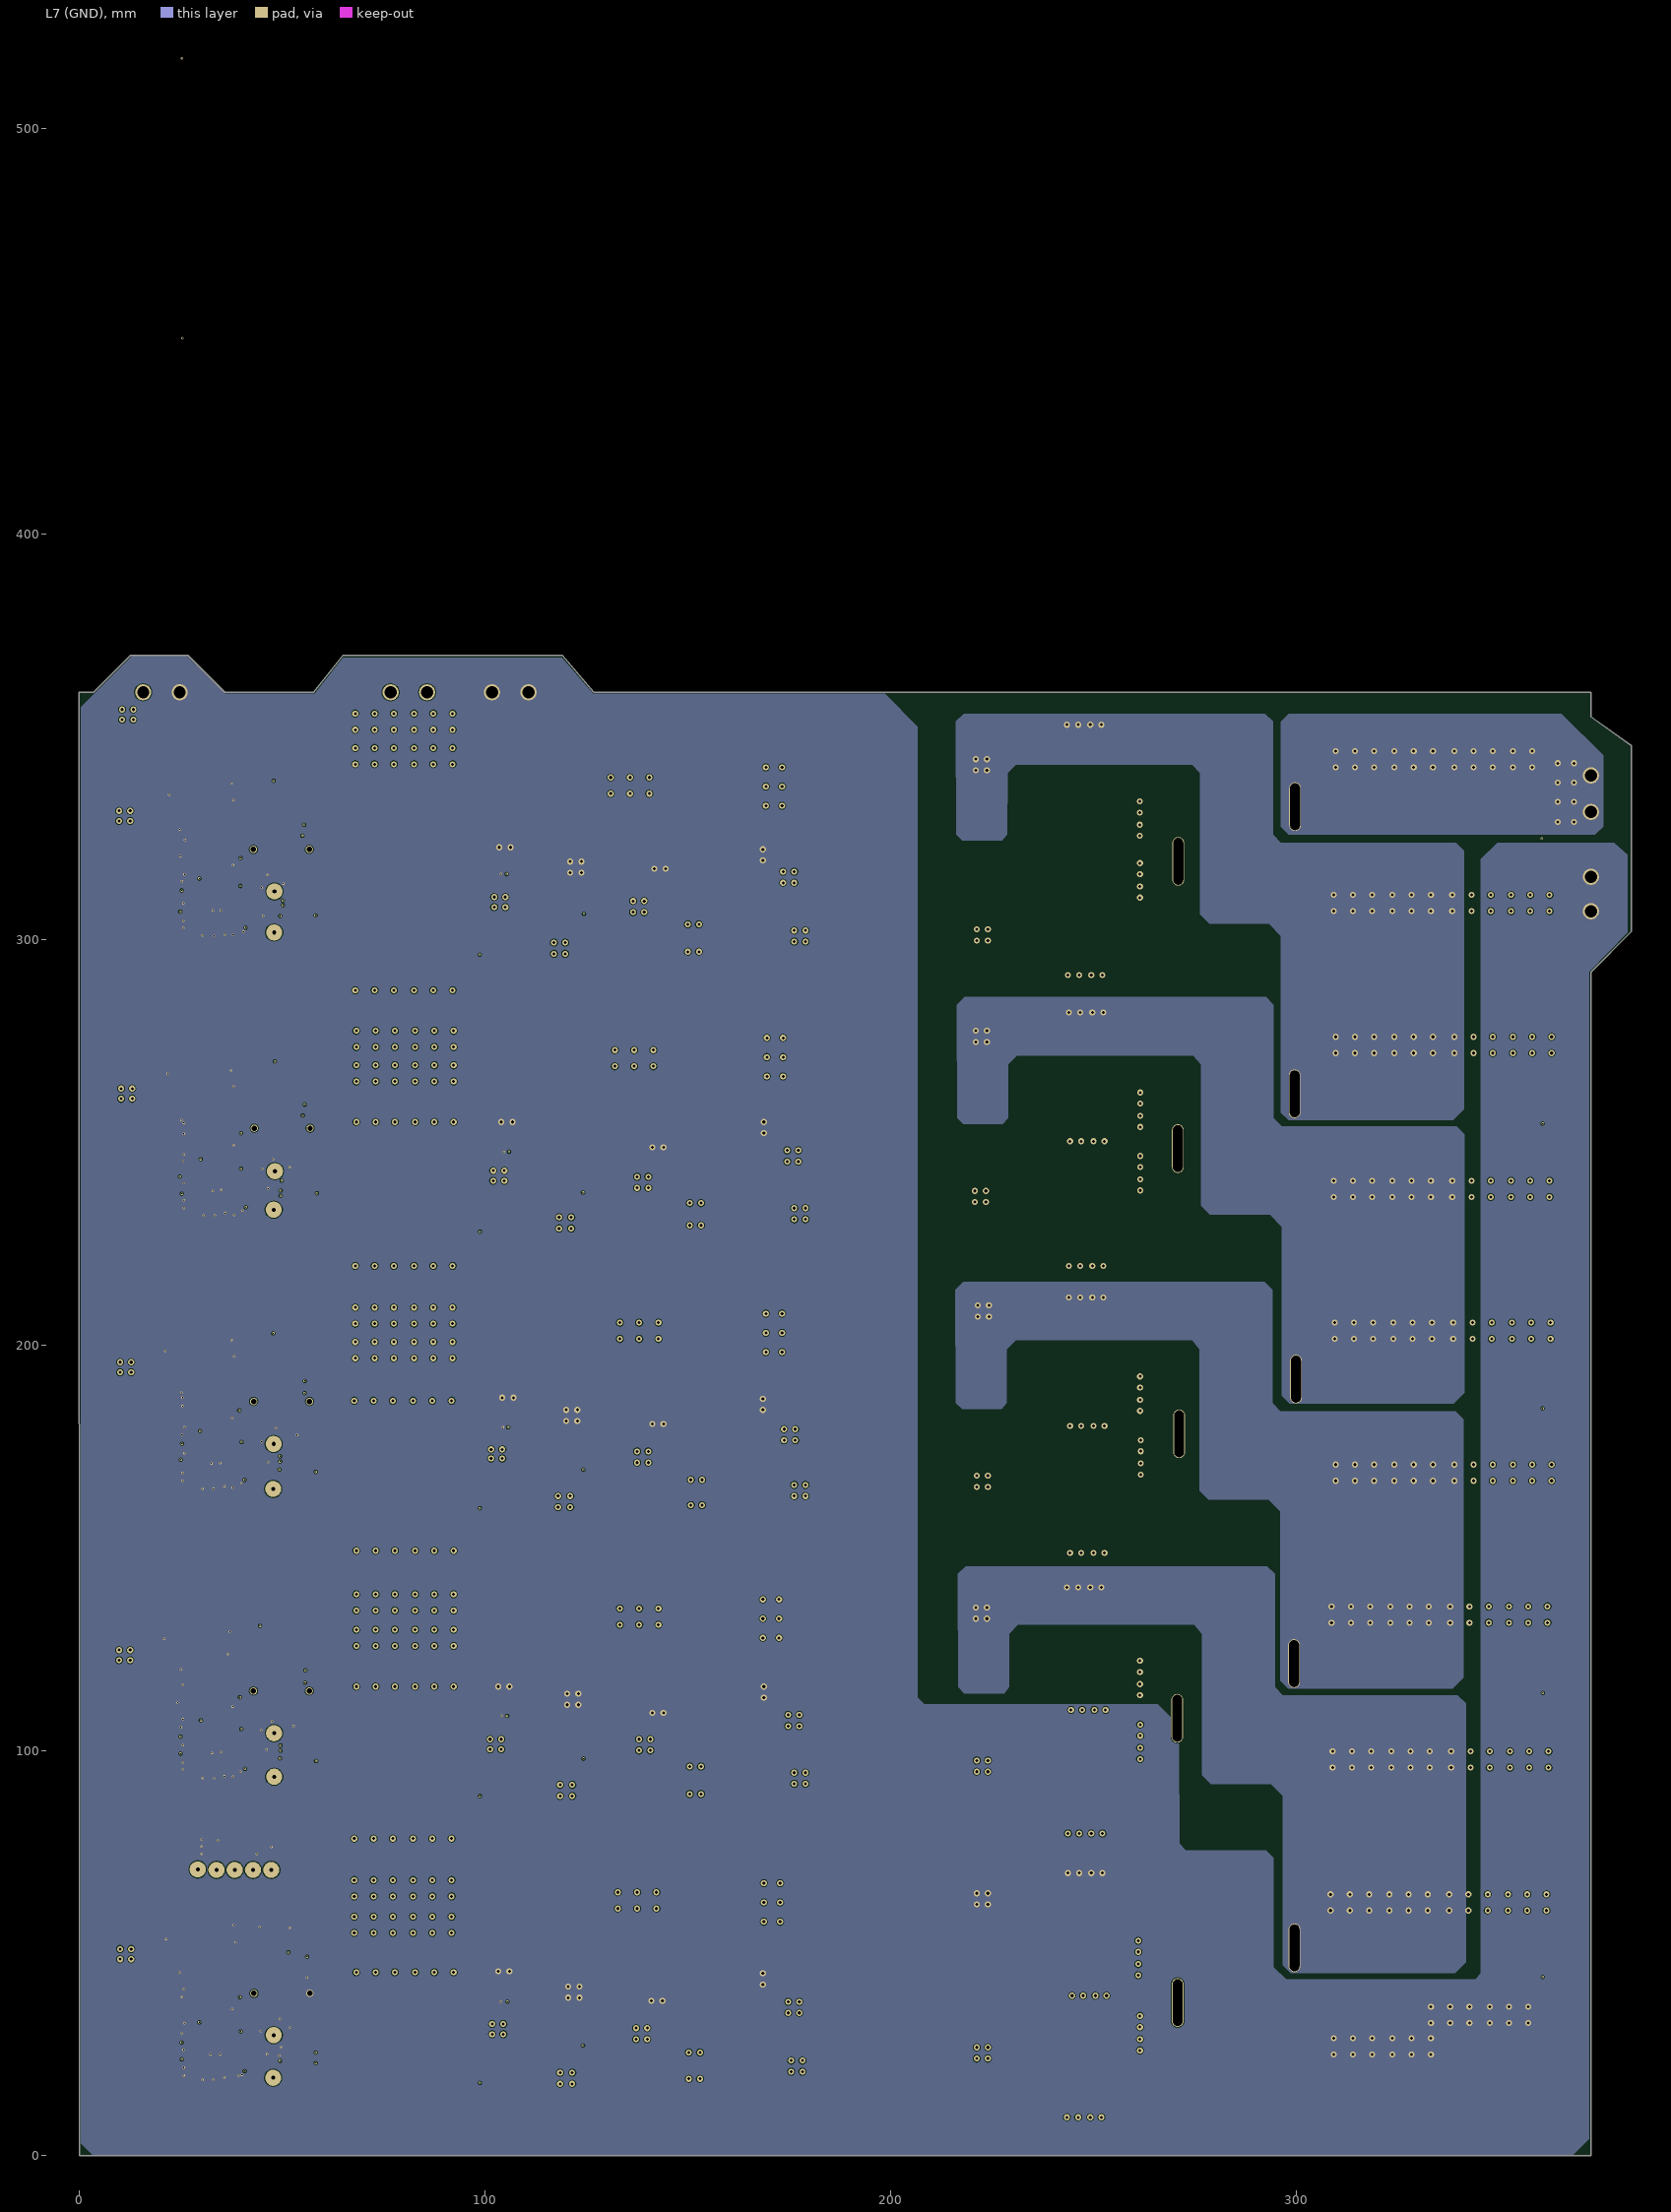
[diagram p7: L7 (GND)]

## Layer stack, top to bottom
Top Solder: solder mask 0.0102, Solder Resist, Dk 3.5
L1: signal copper 0.0356
Dielectric 5: prepreg 0.0711, PP-006, Dk 4.1
L2 (GND): signal copper 0.035
Dielectric 4: prepreg 0.0711, PP-006, Dk 4.1
L3: signal copper 0.035
Dielectric 2: prepreg 0.0711, PP-006, Dk 4.1
L4: signal copper 0.035
Dielectric 7: prepreg 0.0711, PP-006, Dk 4.1
L5(GND): signal copper 0.035
Dielectric 6: prepreg 0.0711, PP-006, Dk 4.1
L6: signal copper 0.035
Dielectric 1: dielectric 0.32, FR-4, Dk 4.8
L7 (GND): signal copper 0.035
Dielectric 3: prepreg 0.0711, PP-006, Dk 4.1
L8: signal copper 0.0356
Bottom Solder: solder mask 0.0102, Solder Resist, Dk 3.5

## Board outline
372.7,355 382.632,347.905 382.632,301.932 372.7,292 372.7,0 -0.012,0 -0.173,361 3.455,361 12.577,370.123 26.7,370.123 35.823,361 57.7,361 65.009,370.123 119.031,370.123 126.829,361 372.7,361

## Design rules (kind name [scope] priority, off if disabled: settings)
AcuteAngle [All] p1: minimum=8.80000000000000E+0001 checktracksonly=FALSE
Clearance [All] p1: gap=0.2 ignorepadtopadclearanceinfootprint=TRUE
ComponentClearance [All] p1: gap=0.099 collisioncheckmode=3 verticalgap=0.099 showdistances=FALSE
HoleSize [All] p1: absolutevalues=TRUE maxlimit=100 minlimit=0.025 maxpercent=80.000 minpercent=20.000
MinimumSolderMaskSliver [All] p1: minsoldermaskwidth=0.1
PolygonConnect PolygonConnect_1 [All vs IsNamedPolygon('+3.3V_L01_P420') Or IsNamedPolygon('+PH2_L01_P407') Or IsNamedPolygon('+PH3_L01_P413') Or IsNamedPolygon('+PH4_L01_P414') Or IsNamedPolygon('+PH5_L01_P415') Or IsNamedPolygon('GND_L01_P284') Or IsNamedPolygon('GND_L01_P396') Or IsNamedPolygon('GND_L01_P398') Or IsNamedPolygon('GND_L01_P400') Or IsNamedPolygon('GND_L01_P402') Or IsNamedPolygon('GND_L01_P408') Or IsNamedPolygon('GND_L01_P409') Or IsNamedPolygon('GND_L01_P410') Or IsNamedPolygon('GND_L01_P411') Or IsNamedPolygon('GND_L01_P412') Or IsNamedPolygon('GND_L01_P416') Or IsNamedPolygon('L1-+12V') Or IsNamedPolygon('L1-+PH2') Or IsNamedPolygon('L1-+PH2') Or IsNamedPolygon('L1-+PH2') Or IsNamedPolygon('L1-+PH2') Or IsNamedPolygon('L1-+PH2') Or IsNamedPolygon('L1-+PH2') Or IsNamedPolygon('L1-+PH2') Or IsNamedPolygon('L1-+PH2') Or IsNamedPolygon('L1-+PH2') Or IsNamedPolygon('L1-+PH2') Or IsNamedPolygon('L1-+PH3') Or IsNamedPolygon('L1-+PH4') Or IsNamedPolygon('L1-+PH5') Or IsNamedPolygon('L1-+PH2 1') Or IsNamedPolygon('L1-NetC2_1') Or IsNamedPolygon('L1-NetC2_1') Or IsNamedPolygon('L1-No Net') Or IsNamedPolygon('NETC11_1_L01_P265') Or IsNamedPolygon('NETC11_2_L01_P270') Or IsNamedPolygon('NETC11_2_L01_P272') Or IsNamedPolygon('NETC12_1_L01_P278') Or IsNamedPolygon('NETC17_2_L01_P406') Or IsNamedPolygon('NETC23_2_L01_P277') Or IsNamedPolygon('NETC27_2_L01_P418') Or IsNamedPolygon('NETC31_2_L01_P417') Or IsNamedPolygon('NETC33_2_L01_P419') Or IsNamedPolygon('NETC52_1_L01_P359') Or IsNamedPolygon('NETC52_2_L01_P276') Or IsNamedPolygon('NETC52_2_L01_P360') Or IsNamedPolygon('NETC53_1_L01_P386') Or IsNamedPolygon('NETC58_2_L01_P405') Or IsNamedPolygon('NETC75_1_L01_P388') Or IsNamedPolygon('NETC75_2_L01_P274') Or IsNamedPolygon('NETC75_2_L01_P363') Or IsNamedPolygon('NETC76_1_L01_P389') Or IsNamedPolygon('NETC81_2_L01_P404') Or IsNamedPolygon('NETC98_1_L01_P391') Or IsNamedPolygon('NETC98_2_L01_P273') Or IsNamedPolygon('NETC98_2_L01_P366') Or IsNamedPolygon('NETC99_1_L01_P392') Or IsNamedPolygon('NETC104_2_L01_P403') Or IsNamedPolygon('NETC121_1_L01_P269') Or IsNamedPolygon('NETC121_2_L01_P275') Or IsNamedPolygon('NETC121_2_L01_P369') Or IsNamedPolygon('NETC122_1_L01_P395') Or IsNamedPolygon('NETC127_2_L01_P381') Or IsNamedPolygon('NETD1_4_L01_P294') Or IsNamedPolygon('NETD5_4_L01_P343') Or IsNamedPolygon('NETD9_4_L01_P297') Or IsNamedPolygon('NETD13_4_L01_P298') Or IsNamedPolygon('NETD17_4_L01_P299') Or IsNamedPolygon('NETNMOS1_1_L01_P264') Or IsNamedPolygon('NETNMOS2_1_L01_P316') Or IsNamedPolygon('NETNMOS3_1_L01_P317') Or IsNamedPolygon('NETNMOS4_1_L01_P318') Or IsNamedPolygon('NETNMOS5_1_L01_P319') Or IsNamedPolygon('NONET_L01_P271') Or IsNamedPolygon('GND_L02_P421') Or IsNamedPolygon('GND_L03_P582') Or IsNamedPolygon('GND_L03_P621') Or IsNamedPolygon('GND_L03_P622') Or IsNamedPolygon('GND_L03_P623') Or IsNamedPolygon('GND_L03_P624') Or IsNamedPolygon('L1-+PH2') Or IsNamedPolygon('L1-+PH2') Or IsNamedPolygon('L1-+PH2') Or IsNamedPolygon('L1-+PH2') Or IsNamedPolygon('L1-+PH2') Or IsNamedPolygon('L1-+PH2') Or IsNamedPolygon('L1-+PH2') Or IsNamedPolygon('L1-+PH2') Or IsNamedPolygon('L1-+PH2') Or IsNamedPolygon('L1-+PH2') Or IsNamedPolygon('L1-NetC2_1') Or IsNamedPolygon('L1-NetC2_1') Or IsNamedPolygon('L1-No Net') Or IsNamedPolygon('L3-+12V') Or IsNamedPolygon('L3-+PH2') Or IsNamedPolygon('L3-+PH3') Or IsNamedPolygon('L3-+PH4') Or IsNamedPolygon('L3-+PH5') Or IsNamedPolygon('NETC11_1_L03_P572') Or IsNamedPolygon('NETC11_2_L03_P574') Or IsNamedPolygon('NETC11_2_L03_P576') Or IsNamedPolygon('NETC12_1_L03_P581') Or IsNamedPolygon('NETC52_1_L03_P609') Or IsNamedPolygon('NETC52_2_L03_P580') Or IsNamedPolygon('NETC52_2_L03_P610') Or IsNamedPolygon('NETC53_1_L03_P615') Or IsNamedPolygon('NETC75_1_L03_P616') Or IsNamedPolygon('NETC75_2_L03_P578') Or IsNamedPolygon('NETC75_2_L03_P611') Or IsNamedPolygon('NETC76_1_L03_P617') Or IsNamedPolygon('NETC98_1_L03_P618') Or IsNamedPolygon('NETC98_2_L03_P577') Or IsNamedPolygon('NETC98_2_L03_P612') Or IsNamedPolygon('NETC99_1_L03_P619') Or IsNamedPolygon('NETC121_1_L03_P573') Or IsNamedPolygon('NETC121_2_L03_P579') Or IsNamedPolygon('NETC121_2_L03_P613') Or IsNamedPolygon('NETC122_1_L03_P620') Or IsNamedPolygon('NETD1_4_L03_P585') Or IsNamedPolygon('NETD5_4_L03_P600') Or IsNamedPolygon('NETD9_4_L03_P586') Or IsNamedPolygon('NETD13_4_L03_P587') Or IsNamedPolygon('NETD17_4_L03_P588') Or IsNamedPolygon('NETNMOS1_1_L03_P571') Or IsNamedPolygon('NETNMOS2_1_L03_P593') Or IsNamedPolygon('NETNMOS3_1_L03_P594') Or IsNamedPolygon('NETNMOS4_1_L03_P595') Or IsNamedPolygon('NETNMOS5_1_L03_P596') Or IsNamedPolygon('NONET_L03_P575') Or IsNamedPolygon('GND_L04_P798') Or IsNamedPolygon('GND_L04_P837') Or IsNamedPolygon('GND_L04_P838') Or IsNamedPolygon('GND_L04_P839') Or IsNamedPolygon('GND_L04_P840') Or IsNamedPolygon('L1-+PH2') Or IsNamedPolygon('L1-+PH2') Or IsNamedPolygon('L1-+PH2') Or IsNamedPolygon('L1-+PH2') Or IsNamedPolygon('L1-+PH2') Or IsNamedPolygon('L1-+PH2') Or IsNamedPolygon('L1-+PH2') Or IsNamedPolygon('L1-+PH2') Or IsNamedPolygon('L1-+PH2') Or IsNamedPolygon('L1-+PH2') Or IsNamedPolygon('L1-NetC2_1') Or IsNamedPolygon('L1-NetC2_1') Or IsNamedPolygon('L1-No Net') Or IsNamedPolygon('L4-+12V') Or IsNamedPolygon('L4-+PH2') Or IsNamedPolygon('L4-+PH3') Or IsNamedPolygon('L4-+PH4') Or IsNamedPolygon('L4-+PH5') Or IsNamedPolygon('NETC11_1_L04_P788') Or IsNamedPolygon('NETC11_2_L04_P790') Or IsNamedPolygon('NETC11_2_L04_P792') Or IsNamedPolygon('NETC12_1_L04_P797') Or IsNamedPolygon('NETC52_1_L04_P825') Or IsNamedPolygon('NETC52_2_L04_P796') Or IsNamedPolygon('NETC52_2_L04_P826') Or IsNamedPolygon('NETC53_1_L04_P831') Or IsNamedPolygon('NETC75_1_L04_P832') Or IsNamedPolygon('NETC75_2_L04_P794') Or IsNamedPolygon('NETC75_2_L04_P827') Or IsNamedPolygon('NETC76_1_L04_P833') Or IsNamedPolygon('NETC98_1_L04_P834') Or IsNamedPolygon('NETC98_2_L04_P793') Or IsNamedPolygon('NETC98_2_L04_P828') Or IsNamedPolygon('NETC99_1_L04_P835') Or IsNamedPolygon('NETC121_1_L04_P789') Or IsNamedPolygon('NETC121_2_L04_P795') Or IsNamedPolygon('NETC121_2_L04_P829') Or IsNamedPolygon('NETC122_1_L04_P836') Or IsNamedPolygon('NETD1_4_L04_P801') Or IsNamedPolygon('NETD5_4_L04_P816') Or IsNamedPolygon('NETD9_4_L04_P802') Or IsNamedPolygon('NETD13_4_L04_P803') Or IsNamedPolygon('NETD17_4_L04_P804') Or IsNamedPolygon('NETNMOS1_1_L04_P787') Or IsNamedPolygon('NETNMOS2_1_L04_P809') Or IsNamedPolygon('NETNMOS3_1_L04_P810') Or IsNamedPolygon('NETNMOS4_1_L04_P811') Or IsNamedPolygon('NETNMOS5_1_L04_P812') Or IsNamedPolygon('NONET_L04_P791') Or IsNamedPolygon('L1-+PH2') Or IsNamedPolygon('L1-+PH2') Or IsNamedPolygon('L1-+PH2') Or IsNamedPolygon('L1-+PH2') Or IsNamedPolygon('L1-+PH2') Or IsNamedPolygon('L1-+PH2') Or IsNamedPolygon('L1-+PH2') Or IsNamedPolygon('L1-+PH2') Or IsNamedPolygon('L1-+PH2') Or IsNamedPolygon('L1-+PH2') Or IsNamedPolygon('L1-NetC2_1') Or IsNamedPolygon('L1-NetC2_1') Or IsNamedPolygon('L5-+PH2') Or IsNamedPolygon('L5-+PH3') Or IsNamedPolygon('L5-+PH4') Or IsNamedPolygon('L5-+PH5') Or IsNamedPolygon('NETD1_4_L05_P855') Or IsNamedPolygon('NETD5_4_L05_P870') Or IsNamedPolygon('NETD9_4_L05_P856') Or IsNamedPolygon('NETD13_4_L05_P857') Or IsNamedPolygon('NETD17_4_L05_P858') Or IsNamedPolygon('GND_L06_P485') Or IsNamedPolygon('L1-+PH2') Or IsNamedPolygon('L1-+PH2') Or IsNamedPolygon('L1-+PH2') Or IsNamedPolygon('L1-+PH2') Or IsNamedPolygon('L1-+PH2') Or IsNamedPolygon('L1-+PH2') Or IsNamedPolygon('L1-+PH2') Or IsNamedPolygon('L1-+PH2') Or IsNamedPolygon('L1-+PH2') Or IsNamedPolygon('L1-+PH2') Or IsNamedPolygon('L1-NetC2_1') Or IsNamedPolygon('L1-NetC2_1') Or IsNamedPolygon('L7-+PH2') Or IsNamedPolygon('L7-+PH3') Or IsNamedPolygon('L7-+PH4') Or IsNamedPolygon('L7-+PH5') Or IsNamedPolygon('NETD1_4_L07_P963') Or IsNamedPolygon('NETD5_4_L07_P978') Or IsNamedPolygon('NETD9_4_L07_P964') Or IsNamedPolygon('NETD13_4_L07_P965') Or IsNamedPolygon('NETD17_4_L07_P966')] p1: connectstyle=Direct reliefconductorwidth=0.254 reliefentries=4 polygonreliefangle="90 Angle" airgapwidth=0.254
PolygonConnect [All] p2: connectstyle=Direct reliefconductorwidth=0.254 reliefentries=4 polygonreliefangle="90 Angle" airgapwidth=0.254
RoutingVias [All] p1: holewidth=0.35 width=0.6 viastyle="Through Hole" minholewidth=0.35 minwidth=0.6 maxholewidth=0.35 maxwidth=0.6
SilkToSolderMaskClearance [IsPad] p1: minsilkscreentomaskgap=0.1 clearancetoexposedcopper=TRUE
SolderMaskExpansion [All] p1: expansion=0.102 istentingtop=FALSE
SupplyNets "Schematic Supply Nets_1" [InNet('GND')] p1: voltage=0.000
SupplyNets "Schematic Supply Nets_3" [InNet('+12V')] p2: voltage=0.000
SupplyNets "Schematic Supply Nets_2" [InNet('+3.3V')] p3: voltage=0.000
SupplyNets "Schematic Supply Nets" [InNet('Vin')] p4: voltage=0.000
Width [All] p1: maxlimit=10 minlimit=0.2 preferedwidth=0.2
26 further rules are at their usual default settings.

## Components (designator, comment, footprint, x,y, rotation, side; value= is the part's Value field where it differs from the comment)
C1 "AFK227M2AR44T-F" C_AEC 157.446,334.34 r270 top value=220µF
C2 "AFK227M2AR44T-F" C_AEC 318.146,332.24 r270 top value=220µF
C3 "CAA573X7S2A476M640LH" C_CAA573 143,324.7 r90 top value=47µF
C4 "CAA573X7S2A476M640LH" C_CAA573 134.8,324.7 r90 top value=47µF
C5 "GMC32X7S475K100NT" C_1210 123.4,324.9 r90 top value=4.7µF
C6 "GMC32X7S475K100NT" C_1210 128.3,324.9 r90 top value=4.7µF
C7 "GMC31X7R475K50NT" C_1206 354.6,324.9 r90 top value=4.7µF
C8 "GMC31X7R475K50NT" C_1206 349.7,324.9 r90 top value=4.7µF
C9 "CKG57NX7R1H476M500JJ" C_CKG57N 342.7,324.6 r90 top value=47µF
C10 "CKG57NX7R1H476M500JJ" C_CKG57N 333.6,324.7 r90 top value=47µF
C11 "UUJ2C101MNJ1MS" UUJ2C101MNJ1MS 161.377,300.423 r0 top value=100µF
C12 "ULT2C150MNL1GS" ULT2C150MNL1GS 128.827,295.973 r180 top value=15µF
C13 "CL21B105KBFNNNE" C_0805 42.425,312.925 r180 top value=1µF
C14 "GMC31X7R475K50NT" C_1206 43.6,307.725 r180 top value=4.7µF
C15 "C0603C104K5RACTU" C_0603 42.15,317.225 r0 top value=100nF
C16 "GJM1555C1HR10WB01D" C_0402 54.727,302.623 r180 top value=0.1pF
C17 "GCM1885C1H332FA16D" C_0603 38.127,326.023 r90 top value=3.3nF
C18 "GRM155R61H474KE11D" C_0402 27.227,315.323 r0 top value=470nF
C19 "C0603C103K5RACTU" C_0603 52.127,301.823 r90 top value=10nF
C20 "C0603C104K5RACTU" C_0603 37.927,303.223 r90 top value=100nF
C21 "CL21B105KBFNNNE" C_0805 26.627,326.123 r0 top value=1µF
C22 "GMC55X7R226M50NT" C_2220 44.627,337.223 r270 top value=22µF
C23 "CL21B105KBFNNNE" C_0805 57.577,325.623 r0 top value=1µF
C24 "GMC31X7R475K50NT" C_1206 23.2,333.5 r270 top value=4.7µF
C25 "CL31B106KBHNNNE" C_1206 57.077,329.873 r90 top value=10µF
C26 "GMC31X7R475K50NT" C_1206 23,264.4 r270 top value=4.7µF
C27 "CL31B106KBHNNNE" C_1206 56.87,193.592 r90 top value=10µF
C28 "04026A100KAT2A" C_0402 36.027,337.523 r0 top value=10pF
C29 "04026A100KAT2A" C_0402 35.82,201.242 r0 top value=10pF
C30 "GMC31X7R475K50NT" C_1206 22.92,197.142 r270 top value=4.7µF
C31 "CL31B106KBHNNNE" C_1206 57.18,260.866 r90 top value=10µF
C32 "GMC31X7R475K50NT" C_1206 22.7,125.95 r270 top value=4.7µF
C33 "CL31B106KBHNNNE" C_1206 56.974,122.253 r90 top value=10µF
C34 "04026A100KAT2A" C_0402 36.13,268.516 r0 top value=10pF
C35 "04026A100KAT2A" C_0402 35.424,129.26 r0 top value=10pF
C36 "GMC04X7R104K10NT" C_0402 45.4,74.4 r0 top value=100nF
C37 "GMC04X7R104K10NT" C_0402 31.777,78.023 r0 top value=100nF
C38 "CL31B106KBHNNNE" C_1206 23.15,51.9 r270 top value=10µF
C39 "CKG57NX7R1H476M500JJ" C_CKG57N 51.9,56.9 r90 top value=47µF
C40 "C0603C103K5RACTU" C_0603 45.15,76.15 r180 top value=10nF
C41 "04026A100KAT2A" C_0402 36.4,56.9 r0 top value=10pF
C42 "AFK227M2AR44T-F" C_AEC 157.446,267.64 r270 top value=220µF
C43 "AFK227M2AR44T-F" C_AEC 318.146,262.24 r270 top value=220µF
C44 "CAA573X7S2A476M640LH" C_CAA573 142.8,258.2 r90 top value=47µF
C45 "CAA573X7S2A476M640LH" C_CAA573 134.4,258.1 r90 top value=47µF
C46 "GMC32X7S475K100NT" C_1210 127.9,258.1 r90 top value=4.7µF
C47 "GMC32X7S475K100NT" C_1210 122.9,258.1 r90 top value=4.7µF
C48 "GMC31X7R475K50NT" C_1206 349.7,254.6 r90 top value=4.7µF
C49 "GMC31X7R475K50NT" C_1206 355,254.6 r90 top value=4.7µF
C50 "CKG57NX7R1H476M500JJ" C_CKG57N 333.6,254.4 r90 top value=47µF
C51 "CKG57NX7R1H476M500JJ" C_CKG57N 342.8,254.4 r90 top value=47µF
C52 "UUJ2C101MNJ1MS" UUJ2C101MNJ1MS 161.761,232.24 r0 top value=100µF
C53 "ULT2C150MNL1GS" ULT2C150MNL1GS 129.211,227.79 r180 top value=15µF
C54 "CL21B105KBFNNNE" C_0805 42.45,243.5 r180 top value=1µF
C55 "C0603C104K5RACTU" C_0603 42.53,247.816 r0 top value=100nF
C56 "GMC31X7R475K50NT" C_1206 43.55,238.6 r180 top value=4.7µF
C57 "GJM1555C1HR10WB01D" C_0402 54.83,233.616 r180 top value=0.1pF
C58 "GCM1885C1H332FA16D" C_0603 38.23,257.016 r90 top value=3.3nF
C59 "GRM155R61H474KE11D" C_0402 27.33,246.316 r0 top value=470nF
C60 "C0603C103K5RACTU" C_0603 52.23,232.816 r90 top value=10nF
C61 "C0603C104K5RACTU" C_0603 38.03,234.216 r90 top value=100nF
C62 "CL21B105KBFNNNE" C_0805 26.73,257.116 r0 top value=1µF
C63 "GMC55X7R226M50NT" C_2220 44.73,268.216 r270 top value=22µF
C64 "CL21B105KBFNNNE" C_0805 57.68,256.616 r0 top value=1µF
C65 "AFK227M2AR44T-F" C_AEC 157.446,199.04 r270 top value=220µF
C66 "AFK227M2AR44T-F" C_AEC 319.146,191.59 r270 top value=220µF
C67 "CAA573X7S2A476M640LH" C_CAA573 134.5,190.1 r90 top value=47µF
C68 "CAA573X7S2A476M640LH" C_CAA573 143.1,189.9 r90 top value=47µF
C69 "GMC32X7S475K100NT" C_1210 127.6,190.05 r90 top value=4.7µF
C70 "GMC32X7S475K100NT" C_1210 122.5,190.1 r90 top value=4.7µF
C71 "GMC31X7R475K50NT" C_1206 353.9,184.6 r90 top value=4.7µF
C72 "GMC31X7R475K50NT" C_1206 349.6,184.6 r90 top value=4.7µF
C73 "CKG57NX7R1H476M500JJ" C_CKG57N 334.1,184.4 r90 top value=47µF
C74 "CKG57NX7R1H476M500JJ" C_CKG57N 342.8,184.4 r90 top value=47µF
C75 "UUJ2C101MNJ1MS" UUJ2C101MNJ1MS 161.82,163.892 r0 top value=100µF
C76 "ULT2C150MNL1GS" ULT2C150MNL1GS 129.27,159.442 r180 top value=15µF
C77 "CL21B105KBFNNNE" C_0805 42.575,176.05 r180 top value=1µF
C78 "GMC31X7R475K50NT" C_1206 43.3,171.125 r180 top value=4.7µF
C79 "C0603C104K5RACTU" C_0603 42.22,180.542 r0 top value=100nF
C80 "GJM1555C1HR10WB01D" C_0402 54.52,166.342 r180 top value=0.1pF
C81 "GCM1885C1H332FA16D" C_0603 37.92,189.742 r90 top value=3.3nF
C82 "GRM155R61H474KE11D" C_0402 27.02,179.042 r0 top value=470nF
C83 "C0603C103K5RACTU" C_0603 51.92,165.542 r90 top value=10nF
C84 "C0603C104K5RACTU" C_0603 37.72,166.942 r90 top value=100nF
C85 "CL21B105KBFNNNE" C_0805 26.42,189.842 r0 top value=1µF
C86 "GMC55X7R226M50NT" C_2220 44.42,200.942 r270 top value=22µF
C87 "CL21B105KBFNNNE" C_0805 57.37,189.342 r0 top value=1µF
C88 "AFK227M2AR44T-F" C_AEC 157.446,128.74 r270 top value=220µF
C89 "AFK227M2AR44T-F" C_AEC 317.846,121.44 r270 top value=220µF
C90 "CAA573X7S2A476M640LH" C_CAA573 142.5,119.6 r90 top value=47µF
C91 "CAA573X7S2A476M640LH" C_CAA573 134.1,119.7 r90 top value=47µF
C92 "GMC32X7S475K100NT" C_1210 126.9,119.2 r90 top value=4.7µF
C93 "GMC32X7S475K100NT" C_1210 121.4,119.1 r90 top value=4.7µF
C94 "GMC31X7R475K50NT" C_1206 354.2,114.3 r90 top value=4.7µF
C95 "GMC31X7R475K50NT" C_1206 349.5,114.3 r90 top value=4.7µF
C96 "CKG57NX7R1H476M500JJ" C_CKG57N 333.3,114.1 r90 top value=47µF
C97 "CKG57NX7R1H476M500JJ" C_CKG57N 342.4,114 r90 top value=47µF
C98 "UUJ2C101MNJ1MS" UUJ2C101MNJ1MS 161.874,92.603 r0 top value=100µF
C99 "ULT2C150MNL1GS" ULT2C150MNL1GS 129.324,88.153 r180 top value=15µF
C100 "CL21B105KBFNNNE" C_0805 42.624,105.003 r180 top value=1µF
C101 "C0603C104K5RACTU" C_0603 42.324,109.203 r0 top value=100nF
C102 "GMC31X7R475K50NT" C_1206 43.224,100.303 r180 top value=4.7µF
C103 "GJM1555C1HR10WB01D" C_0402 54.624,95.003 r180 top value=0.1pF
C104 "GCM1885C1H332FA16D" C_0603 38.024,118.403 r90 top value=3.3nF
C105 "GRM155R61H474KE11D" C_0402 27.124,107.703 r0 top value=470nF
C106 "C0603C103K5RACTU" C_0603 52.024,94.203 r90 top value=10nF
C107 "C0603C104K5RACTU" C_0603 37.824,95.603 r90 top value=100nF
C108 "CL21B105KBFNNNE" C_0805 26.7,118.4 r0 top value=1µF
C109 "GMC55X7R226M50NT" C_2220 44.524,129.603 r270 top value=22µF
C110 "CL21B105KBFNNNE" C_0805 57.474,118.003 r0 top value=1µF
C111 "AFK227M2AR44T-F" C_AEC 157.646,57.44 r270 top value=220µF
C112 "AFK227M2AR44T-F" C_AEC 317.846,51.44 r270 top value=220µF
C113 "CAA573X7S2A476M640LH" C_CAA573 142.2,47.95 r90 top value=47µF
C114 "CAA573X7S2A476M640LH" C_CAA573 133.1,47.9 r90 top value=47µF
C115 "GMC32X7S475K100NT" C_1210 125.8,48 r90 top value=4.7µF
C116 "GMC32X7S475K100NT" C_1210 119.8,48 r90 top value=4.7µF
C117 "GMC31X7R475K50NT" C_1206 354.2,44.2 r90 top value=4.7µF
C118 "GMC31X7R475K50NT" C_1206 348.4,44.2 r90 top value=4.7µF
C119 "CKG57NX7R1H476M500JJ" C_CKG57N 333.2,44.1 r90 top value=47µF
C120 "CKG57NX7R1H476M500JJ" C_CKG57N 341.7,44.2 r90 top value=47µF
C121 "UUJ2C101MNJ1MS" UUJ2C101MNJ1MS 161.746,21.868 r0 top value=100µF
C122 "ULT2C150MNL1GS" ULT2C150MNL1GS 129.196,17.418 r180 top value=15µF
C123 "CL21B105KBFNNNE" C_0805 42.4,30.65 r180 top value=1µF
C124 "GMC31X7R475K50NT" C_1206 43.133,25.821 r180 top value=4.7µF
C125 "C0603C104K5RACTU" C_0603 42.025,35.225 r0 top value=100nF
C126 "GJM1555C1HR10WB01D" C_0402 54.533,20.521 r180 top value=0.1pF
C127 "GCM1885C1H332FA16D" C_0603 37.933,43.921 r90 top value=3.3nF
C128 "GRM155R61H474KE11D" C_0402 27.033,33.221 r0 top value=470nF
C129 "C0603C103K5RACTU" C_0603 51.933,19.721 r90 top value=10nF
C130 "C0603C104K5RACTU" C_0603 37.733,21.121 r90 top value=100nF
C131 "CL21B105KBFNNNE" C_0805 26.433,44.021 r0 top value=1µF
C132 "GMC55X7R226M50NT" C_2220 44.4,54.65 r270 top value=22µF
C133 "CL21B105KBFNNNE" C_0805 56.1,46.5 r90 top value=1µF
D1 "DSEP60" D_DSEP60 248.2,299 r0 top
D2 "DSEP60" D_DSEP60 248.27,345.75 r180 top
D3 "B05100W-TP" D_B05100W 51.7,315.25 r270 top
D4 "1N5337BRLG" D_1N5337 49.6,322.2 r0 top
D5 "DSEP60" D_DSEP60 248.27,226.64 r0 top
D6 "DSEP60" D_DSEP60 248.27,273.64 r180 top
D7 "B05100W-TP" D_B05100W 51.7,246.5 r270 top
D8 "1N5337BRLG" D_1N5337 49.8,253.4 r0 top
D9 "DSEP60" D_DSEP60 248.27,156.692 r0 top
D10 "DSEP60" D_DSEP60 248.27,203.692 r180 top
D11 "B05100W-TP" D_B05100W 52.2,179.25 r270 top
D12 "1N5337BRLG" D_1N5337 49.65,186 r0 top
D13 "DSEP60" D_DSEP60 248.27,86.403 r0 top
D14 "DSEP60" D_DSEP60 248.27,133.403 r180 top
D15 "B05100W-TP" D_B05100W 51.7,107.5 r270 top
D16 "1N5337BRLG" D_1N5337 49.6,114.6 r0 top
D17 "DSEP60" D_DSEP60 248.27,16.168 r0 top
D18 "DSEP60" D_DSEP60 248.27,63.168 r180 top
D19 "B05100W-TP" D_B05100W 53.15,33.15 r270 top
D20 "1N5337BRLG" D_1N5337 49.725,40.025 r0 top
J1 "SMTSO-116-8ET" PEM 76.7,361 r0 top
J2 "SMTSO-116-8ET" PEM 85.7,361 r0 top
J3 "SMTSO-116-8ET" PEM 15.7,361 r0 top
J4 "SMTSO-116-8ET" PEM 372.7,340.5 r0 top
J5 "SMTSO-116-8ET" PEM 372.7,331.5 r0 top
J6 "SMTSO-116-8ET" PEM 101.7,361 r0 top
J7 "SMTSO-116-8ET" PEM 110.7,361 r0 top
J8 "SMTSO-116-8ET" PEM 24.7,361 r0 top
J9 "SMTSO-116-8ET" PEM 372.7,315.5 r0 top
J10 "SMTSO-116-8ET" PEM 372.7,307 r0 top
L1 "CPEX4141L-330MC" CPEX4141L-330MC 285.627,324.623 r0 top value=33µF
L2 "CPEX4141L-330MC" CPEX4141L-330MC 285.525,253.775 r0 top value=33µF
L3 "CPEX4141L-330MC" CPEX4141L-330MC 285.85,183.425 r0 top value=33µF
L4 "CPEX4141L-330MC" CPEX4141L-330MC 285.375,113.25 r0 top value=33µF
L5 "CPEX4141L-330MC" CPEX4141L-330MC 285.485,43.125 r0 top value=33µF
NMOS1 "GT100N20TT" GT100N20TT 101.325,305 r0 top
NMOS2 "GT100N20TT" GT100N20TT 101.325,237.25 r0 top
NMOS3 "GT100N20TT" GT100N20TT 101.325,169 r0 top
NMOS4 "GT100N20TT" GT100N20TT 101.325,98 r0 top
NMOS5 "GT100N20TT" GT100N20TT 101.325,27.25 r0 top
PMOS1 "G900P15D5" G900P15 130.107,308.197 r270 top
PMOS2 "G900P15D5" G900P15 130.491,240.014 r270 top
PMOS3 "G900P15D5" G900P15 130.55,171.666 r270 top
PMOS4 "G900P15D5" G900P15 130.604,100.377 r270 top
PMOS5 "G900P15D5" G900P15 130.476,29.642 r270 top
R1 "SMW23R9JT" R_SM2W 142.877,300.423 r0 top value=3.9Ω
R2 "RMCF0805FT82K5" R_0805 26.627,319.523 r180 top value=82.5kΩ
R3 "CRCW08050000Z0EA" R_0805 55.827,315.873 r270 top value=0Ω
R4 "RM04F1002CT" R_0402 47.527,316.423 r90 top value=10kΩ
R5 "RC0603FR-0737K4L" R_0603 26.927,311.023 r180 top value=37.4kΩ
R6 "RC0603FR-0778K7L" R_0603 26.927,306.823 r180 top value=78.7kΩ
R7 "CRCW08050000Z0EA" R_0805 43.227,303.123 r270 top value=0Ω
R8 "RC0603FR-07100RL" R_0603 27.7,328.75 r180 top value=100Ω
R9 "PNM0402E5001BST1" R_0402 40.427,304.123 r0 top value=5kΩ
R10 "CRE2512-FZ-R001E-2" R_2512 104.577,316.373 r90 top value=1mΩ
R11 "PNM0402E5001BST1" R_0402 57.327,302.123 r270 top value=5kΩ
R12 "RMCF0603FT13K3" R_0603 358.5,325.8 r90 top value=13.3kΩ
R13 "RM04F1001CT" R_0402 27.227,304.723 r0 top value=1kΩ
R14 "AC0402FR-073KL" C_0402 40.8,325.9 r90 top value=3kΩ
R15 "RM04F1003CT" R_0402 27.227,317.223 r0 top value=100kΩ
R16 "RM04F1003CT" R_0402 27.227,321.823 r0 top value=100kΩ
R17 "RM04F1001CT" R_0402 27.227,308.923 r0 top value=1kΩ
R18 "RM04F1001CT" R_0402 27.227,323.823 r0 top value=1kΩ
R19 "RM04F1001CT" R_0402 362.4,324.3 r90 top value=1kΩ
R20 "WSC2515500R0FEB" R_WSC2515 49.227,329.823 r0 top value=500Ω
R21 "RC0603FR-07150KL" R_0603 26.927,313.323 r0 top value=150kΩ
R22 "AC0603FR-0775KL" R_0603 35.827,303.373 r90 top value=75kΩ
R23 "RM04F1002CT" R_0402 27.227,302.823 r0 top value=10kΩ
R24 "CRCW08050000Z0EA" R_0805 30.427,303.123 r90 top value=DNI
R25 "CRCW08050000Z0EA" R_0805 33.227,303.123 r90 top value=DNI
R26 "RM06F3481CT" R_0603 36.327,333.523 r0 top value=3.48kΩ
R27 "RM06F3481CT" R_0603 36.12,197.242 r0 top value=3.48kΩ
R28 "RM06F3481CT" R_0603 36.43,264.516 r0 top value=3.48kΩ
R29 "RM06F3481CT" R_0603 35.7,125.25 r0 top value=3.48kΩ
R30 "RM04F1002CT" R_0402 31.777,76.273 r0 top value=10kΩ
R31 "RM04F1002CT" R_0402 31.777,74.523 r0 top value=10kΩ
R32 "RC0603FR-07402KL" R_0603 45.15,78.15 r180 top value=402kΩ
R33 "RK73H1JTTD1182F" R_0603 36.65,52.65 r0 top value=11.8kΩ
R34 "SMW23R9JT" R_SM2W 143.261,232.24 r0 top value=3.9Ω
R35 "RMCF0805FT82K5" R_0805 26.73,250.516 r180 top value=82.5kΩ
R36 "CRCW08050000Z0EA" R_0805 55.93,246.866 r270 top value=0Ω
R37 "RM04F1002CT" R_0402 47.63,247.416 r90 top value=10kΩ
R38 "RC0603FR-0737K4L" R_0603 27.03,242.016 r180 top value=37.4kΩ
R39 "RC0603FR-0778K7L" R_0603 27.03,237.816 r180 top value=78.7kΩ
R40 "CRCW08050000Z0EA" R_0805 43.33,234.116 r270 top value=0Ω
R41 "RC0603FR-07100RL" R_0603 27.7,259.8 r180 top value=100Ω
R42 "PNM0402E5001BST1" R_0402 40.53,235.116 r0 top value=5kΩ
R43 "CRE2512-FZ-R001E-2" R_2512 104.961,248.19 r90 top value=1mΩ
R44 "PNM0402E5001BST1" R_0402 57.43,233.116 r270 top value=5kΩ
R45 "RMCF0603FT13K3" R_0603 358.7,255.5 r90 top value=13.3kΩ
R46 "RM04F1001CT" R_0402 27.33,235.716 r0 top value=1kΩ
R47 "AC0402FR-073KL" C_0402 40.93,256.616 r90 top value=3kΩ
R48 "RM04F1003CT" R_0402 27.33,248.216 r0 top value=100kΩ
R49 "RM04F1003CT" R_0402 27.33,252.816 r0 top value=100kΩ
R50 "RM04F1001CT" R_0402 27.33,239.916 r0 top value=1kΩ
R51 "RM04F1001CT" R_0402 27.33,254.816 r0 top value=1kΩ
R52 "RM04F1001CT" R_0402 362.6,254 r90 top value=1kΩ
R53 "WSC2515500R0FEB" R_WSC2515 49.33,260.816 r0 top value=500Ω
R54 "RC0603FR-07150KL" R_0603 27.03,244.316 r0 top value=150kΩ
R55 "AC0603FR-0775KL" R_0603 35.93,234.366 r90 top value=75kΩ
R56 "RM04F1002CT" R_0402 27.33,233.816 r0 top value=10kΩ
R57 "CRCW08050000Z0EA" R_0805 30.53,234.116 r90 top value=DNI
R58 "CRCW08050000Z0EA" R_0805 33.33,234.116 r90 top value=DNI
R59 "SMW23R9JT" R_SM2W 143.32,163.892 r0 top value=3.9Ω
R60 "RMCF0805FT82K5" R_0805 26.42,183.242 r180 top value=82.5kΩ
R61 "CRCW08050000Z0EA" R_0805 56.275,177.775 r270 top value=0Ω
R62 "RM04F1002CT" R_0402 47.32,180.142 r90 top value=10kΩ
R63 "RC0603FR-0737K4L" R_0603 26.72,174.742 r180 top value=37.4kΩ
R64 "RC0603FR-0778K7L" R_0603 26.72,170.542 r180 top value=78.7kΩ
R65 "CRCW08050000Z0EA" R_0805 43.02,166.842 r270 top value=0Ω
R66 "RC0603FR-07100RL" R_0603 27.45,192.5 r180 top value=100Ω
R67 "PNM0402E5001BST1" R_0402 40.22,167.842 r0 top value=5kΩ
R68 "CRE2512-FZ-R001E-2" R_2512 105,179.7 r90 top value=1mΩ
R69 "PNM0402E5001BST1" R_0402 57.12,165.842 r270 top value=5kΩ
R70 "RMCF0603FT13K3" R_0603 358.683,185.253 r90 top value=13.3kΩ
R71 "RM04F1001CT" R_0402 27.02,168.442 r0 top value=1kΩ
R72 "AC0402FR-073KL" C_0402 40.62,189.342 r90 top value=3kΩ
R73 "RM04F1003CT" R_0402 27.02,180.942 r0 top value=100kΩ
R74 "RM04F1003CT" R_0402 27.02,185.542 r0 top value=100kΩ
R75 "RM04F1001CT" R_0402 27.02,172.642 r0 top value=1kΩ
R76 "RM04F1001CT" R_0402 27.02,187.542 r0 top value=1kΩ
R77 "RM04F1001CT" R_0402 362.583,183.753 r90 top value=1kΩ
R78 "WSC2515500R0FEB" R_WSC2515 49.02,193.542 r0 top value=500Ω
R79 "RC0603FR-07150KL" R_0603 26.72,177.042 r0 top value=150kΩ
R80 "AC0603FR-0775KL" R_0603 35.62,167.092 r90 top value=75kΩ
R81 "RM04F1002CT" R_0402 27.02,166.542 r0 top value=10kΩ
R82 "CRCW08050000Z0EA" R_0805 30.22,166.842 r90 top value=DNI
R83 "CRCW08050000Z0EA" R_0805 33.02,166.842 r90 top value=DNI
R84 "SMW23R9JT" R_SM2W 143.374,92.603 r0 top value=3.9Ω
R85 "RMCF0805FT82K5" R_0805 26.524,111.903 r180 top value=82.5kΩ
R86 "CRCW08050000Z0EA" R_0805 55.45,106.25 r270 top value=0Ω
R87 "RM04F1002CT" R_0402 47.45,108.75 r90 top value=10kΩ
R88 "RC0603FR-0737K4L" R_0603 26.824,103.403 r180 top value=37.4kΩ
R89 "RC0603FR-0778K7L" R_0603 26.824,99.203 r180 top value=78.7kΩ
R90 "CRCW08050000Z0EA" R_0805 43.124,95.503 r270 top value=0Ω
R91 "RC0603FR-07100RL" R_0603 27.1,121.4 r180 top value=100Ω
R92 "PNM0402E5001BST1" R_0402 40.324,96.503 r0 top value=5kΩ
R93 "CRE2512-FZ-R001E-2" R_2512 104.8,108.4 r90 top value=1mΩ
R94 "PNM0402E5001BST1" R_0402 57.224,94.503 r270 top value=5kΩ
R95 "RMCF0603FT13K3" R_0603 358.75,115.05 r90 top value=13.3kΩ
R96 "RM04F1001CT" R_0402 27.124,97.103 r0 top value=1kΩ
R97 "AC0402FR-073KL" C_0402 40.724,118.003 r90 top value=3kΩ
R98 "RM04F1003CT" R_0402 27.124,109.603 r0 top value=100kΩ
R99 "RM04F1003CT" R_0402 27.1,114.2 r0 top value=100kΩ
R100 "RM04F1001CT" R_0402 27.124,101.303 r0 top value=1kΩ
R101 "RM04F1001CT" R_0402 27.1,116.1 r0 top value=1kΩ
R102 "RM04F1001CT" R_0402 362.65,113.55 r90 top value=1kΩ
R103 "WSC2515500R0FEB" R_WSC2515 49.124,122.203 r0 top value=500Ω
R104 "RC0603FR-07150KL" R_0603 26.824,105.703 r0 top value=150kΩ
R105 "AC0603FR-0775KL" R_0603 35.724,95.753 r90 top value=75kΩ
R106 "RM04F1002CT" R_0402 27.124,95.203 r0 top value=10kΩ
R107 "CRCW08050000Z0EA" R_0805 30.324,95.503 r90 top value=DNI
R108 "CRCW08050000Z0EA" R_0805 33.124,95.503 r90 top value=DNI
R109 "SMW23R9JT" R_SM2W 143.246,21.868 r0 top value=3.9Ω
R110 "RMCF0805FT82K5" R_0805 26.433,37.421 r180 top value=82.5kΩ
R111 "CRCW08050000Z0EA" R_0805 57.4,31.45 r270 top value=0Ω
R112 "RM04F1002CT" R_0402 48.15,34.4 r90 top value=10kΩ
R113 "RC0603FR-0737K4L" R_0603 26.733,28.921 r180 top value=37.4kΩ
R114 "RC0603FR-0778K7L" R_0603 26.733,24.721 r180 top value=78.7kΩ
R115 "CRCW08050000Z0EA" R_0805 43.033,21.021 r270 top value=0Ω
R116 "RC0603FR-07100RL" R_0603 27.9,47.9 r180 top value=100Ω
R117 "PNM0402E5001BST1" R_0402 40.233,22.021 r0 top value=5kΩ
R118 "CRE2512-FZ-R001E-2" R_2512 104.95,38 r90 top value=1mΩ
R119 "PNM0402E5001BST1" R_0402 57.133,20.021 r270 top value=5kΩ
R120 "RMCF0603FT13K3" R_0603 358.65,44.95 r90 top value=13.3kΩ
R121 "RM04F1001CT" R_0402 27.033,22.621 r0 top value=1kΩ
R122 "AC0402FR-073KL" C_0402 40.525,42.75 r90 top value=3kΩ
R123 "RM04F1003CT" R_0402 27.033,35.121 r0 top value=100kΩ
R124 "RM04F1003CT" R_0402 27.033,39.721 r0 top value=100kΩ
R125 "RM04F1001CT" R_0402 27.033,26.821 r0 top value=1kΩ
R126 "RM04F1001CT" R_0402 27.033,41.721 r0 top value=1kΩ
R127 "RM04F1001CT" R_0402 362.55,43.45 r90 top value=1kΩ
R128 "WSC2515500R0FEB" R_WSC2515 48.675,47.025 r0 top value=500Ω
R129 "RC0603FR-07150KL" R_0603 26.733,31.221 r0 top value=150kΩ
R130 "AC0603FR-0775KL" R_0603 35.633,21.271 r90 top value=75kΩ
R131 "RM04F1002CT" R_0402 27.033,20.721 r0 top value=10kΩ
R132 "CRCW08050000Z0EA" R_0805 30.233,21.021 r90 top value=DNI
R133 "CRCW08050000Z0EA" R_0805 33.033,21.021 r90 top value=DNI
T1 "TEST" TEST_POINT 48.077,311.873 r90 top
T2 "TEST" TEST_POINT 48,301.75 r90 top
T3 "TEST" TEST_POINT 29.15,70.65 r90 top
T4 "TEST" TEST_POINT 48.18,242.866 r90 top
T5 "TEST" TEST_POINT 47.875,233.375 r90 top
T6 "TEST" TEST_POINT 33.777,70.523 r90 top
T7 "TEST" TEST_POINT 47.87,175.592 r90 top
T8 "TEST" TEST_POINT 47.75,164.5 r90 top
T9 "TEST" TEST_POINT 38.277,70.523 r90 top
T10 "TEST" TEST_POINT 47.974,104.253 r90 top
T11 "TEST" TEST_POINT 48,93.5 r90 top
T12 "TEST" TEST_POINT 42.777,70.523 r90 top
T13 "TEST" TEST_POINT 47.883,29.771 r90 top
T14 "TEST" TEST_POINT 47.75,19.25 r90 top
T15 "TEST" TEST_POINT 47.277,70.523 r90 top
TRAN1 "NA5871-AL" NA5871-AL 199.577,324.223 r0 top
TRAN2 "NA5871-AL" NA5871-AL 199.961,256.04 r0 top
TRAN3 "NA5871-AL" NA5871-AL 200.02,187.692 r0 top
TRAN4 "NA5871-AL" NA5871-AL 200.074,116.403 r0 top
TRAN5 "NA5871-AL" NA5871-AL 199.946,45.668 r0 top
U1 "LT3753HFE#PBF" LT3753 35.271,313.1 r0 top
U2 "PS2801C-1-F3-A" PS2801C 34.827,321.823 r0 top
U3 "LT1431CS8#TRPBF" LT1431 54.077,306.873 r180 top
U4 "LTM8067EY#PBF" LTM8067 29.477,336.173 r0 top
U5 "LTM8067EY#PBF" LTM8067 29.27,199.892 r0 top
U6 "LTM8067EY#PBF" LTM8067 29.58,267.166 r0 top
U7 "LTM8067EY#PBF" LTM8067 29.2,128.8 r0 top
U8 "LTM8067EY#PBF" LTM8067 29.613,55.272 r0 top
U9 "LTC6909HMS#TRPBF" LTC6909 38.277,76.273 r0 top
U10 "LT3753HFE#PBF" LT3753 35.374,244.093 r0 top
U11 "PS2801C-1-F3-A" PS2801C 34.93,252.816 r0 top
U12 "LT1431CS8#TRPBF" LT1431 54.18,237.866 r180 top
U13 "LT3753HFE#PBF" LT3753 35.064,176.819 r0 top
U14 "PS2801C-1-F3-A" PS2801C 34.62,185.542 r0 top
U15 "LT1431CS8#TRPBF" LT1431 53.87,170.592 r180 top
U16 "LT3753HFE#PBF" LT3753 35.168,105.48 r0 top
U17 "PS2801C-1-F3-A" PS2801C 34.724,114.203 r0 top
U18 "LT1431CS8#TRPBF" LT1431 53.974,99.253 r180 top
U19 "LT3753HFE#PBF" LT3753 35.077,30.998 r0 top
U20 "PS2801C-1-F3-A" PS2801C 34.633,39.721 r0 top
U21 "LT1431CS8#TRPBF" LT1431 53.883,24.771 r180 top

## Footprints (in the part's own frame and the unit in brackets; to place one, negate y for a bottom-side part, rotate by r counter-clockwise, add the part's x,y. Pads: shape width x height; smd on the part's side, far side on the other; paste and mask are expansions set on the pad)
C_0402 [mm]
  rect 0.5x0.5 smd: 1(-0.5,0) 2(0.508,0)
  silkscreen extent -1.1,-0.6 1.1,0.6
C_0603 [mm]
  rect 0.8x0.8 smd: 1(-0.75,0) 2(0.75,0)
  silkscreen extent -1.5,-0.7 1.5,0.7
C_0805 [mm]
  rect 0.9x1.3 smd: 1(-0.95,0) 2(0.95,0)
  silkscreen extent -1.8,-1 1.8,1
C_1206 [mm]
  rect 0.9x1.6 smd: 1(-1.55,0) 2(1.55,0)
  silkscreen extent -2.4,-1.2 2.4,1.2
C_1210 [mm]
  rect 0.9x2.5 smd: 1(-1.55,0) 2(1.55,0)
  silkscreen extent -2.4,-1.7 2.4,1.7
C_2220 [mm]
  rect 0.9x5.6 smd: 1(-2.8,0) 2(2.8,0)
  silkscreen extent -3.9,-3.5 3.9,3.5
C_AEC [mm]
  rect 7.5x2.5 smd: 1(0.24,0.054) 2(15.34,0.054)
  silkscreen extent -1.7,-9.45 17.3,9.6, body extent -2.71,-9.55 18.29,9.65, height 17
C_CAA573 [mm]
  rect 1.4x5.5 smd: 1(-2.55,0) 2(2.55,0)
  silkscreen extent -4,-3.4 4,3.4
C_CKG57N [mm]
  rect 1.9x5.5 smd: 1(-2.3,0) 2(2.3,0)
  silkscreen extent -3.9,-3.3 4,3.3
CPEX4141L-330MC [mm]
  oval 2.896x12.014 hole 11.5 slot 2.388 at 0 deg paste-2539.97 mask+0: 1(-14.685,-5.325) 2(14.115,8.175)
  silkscreen extent -21.92,-19.71 20.34,22.56
D_1N5337 [mm]
  round 1.8 hole 1.3: 1(-6.71,0.053) 2(7.064,0.053)
  silkscreen extent -5.41,-1.69 5.76,1.8
D_B05100W [mm]
  rect 0.2x0.65 smd: 1(1.5,0) 2(-1.5,0)
  silkscreen extent -2.2,-0.8 2.2,0.8
D_DSEP60 [mm]
  rect 2.5x3 smd: 1(-4.25,0) 3(4.25,0)
  rect 17x13 smd: 4(0,13)
  silkscreen extent -10,-2.5 10,20.7
G900P15 [mm]
  rect 0.5x0.65 smd: 1(-1.931,-3.745) 2(-0.661,-3.745) 3(0.609,-3.745) 4(1.879,-3.745)
  rect 0.5x0.55 smd: 5(-1.931,1.805) 6(-0.661,1.805) 7(0.609,1.805) 8(1.879,1.805)
  rect 4.6x4.12 smd: 8(-0.026,-0.53)
  silkscreen extent -3.6,-5.1 3.6,3.1, body extent -2.7,-3.89 2.65,2.16, height 1.05
GT100N20TT [mm]
  rect 2.55x0.9 smd: 1(0,0) 2(0,-1.25) 3(0,-2.5) 4(0,-3.75) 5(0,-5) 6(0,-6.25) 7(0,-7.5) 8(0,-8.75) 9(13.375,-8.75) 10(13.375,-7.5) 11(13.375,-6.25) 12(13.375,-5) 13(13.375,-3.75) 14(13.375,-2.5) 15(13.375,-1.25) 16(13.375,0)
  silkscreen extent -0.1,-9.35 11.7,1.17, body extent 1.55,-9.35 11.85,0.75, height 2.35
LT1431 [mm]
  rect 1.526x0.65 smd: 1(-2.692,1.863) 2(-2.692,0.593) 3(-2.692,-0.677) 4(-2.692,-1.947) 5(2.732,-1.947) 6(2.732,-0.677) 7(2.732,0.593) 8(2.732,1.863)
  silkscreen extent -3.45,-2.49 1.62,2.54, body extent -2.98,-2.49 3.02,2.41, height 1.75
LT3753 [mm]
  rrect25% 1.5x0.28 smd mask+0.05: 1(-3.244,4.123) 2(-3.244,3.623) 3(-3.244,3.123) 4(-3.244,2.623) 5(-3.244,2.123) 6(-3.244,1.623) 7(-3.244,1.123) 8(-3.244,0.623) 9(-3.244,0.123) 10(-3.244,-0.377) 11(-3.244,-0.877) 12(-3.244,-1.377) 13(-3.244,-1.877) 14(-3.244,-2.377) 15(-3.244,-2.877) 16(-3.244,-3.377) 17(-3.244,-3.877) 18(-3.244,-4.377) 19(-3.244,-4.877) 20(2.586,-4.877) 21(2.586,-4.377) 22(2.586,-3.877) 24(2.586,-2.877) 26(2.586,-1.877) 28(2.586,-0.877) 30(2.586,0.123) 32(2.586,1.123) 34(2.586,2.123) 36(2.586,3.123) 37(2.586,3.623) 38(2.586,4.123)
  rect 2.74x4.75 smd paste-3: 39(-0.329,-0.377)
  silkscreen extent -4.94,-5.23 1.87,4.6
LTC6909 [mm]
  rect 1.425x0.3 smd mask+0.05: 1(-2.29,1.84) 2(-2.29,1.34) 3(-2.29,0.84) 4(-2.29,0.34) 5(-2.29,-0.16) 6(-2.29,-0.66) 7(-2.29,-1.16) 8(-2.29,-1.66) 9(2.134,-1.66) 10(2.134,-1.16) 11(2.134,-0.66) 12(2.134,-0.16) 13(2.134,0.34) 14(2.134,0.84) 15(2.134,1.34) 16(2.134,1.84)
  silkscreen extent -3,-1.93 1.07,2.34, body extent -2.53,-1.93 2.37,2.11, height 1.1
LTM8067 [mm]
  round 0.612 smd: A1(-3.813,3.958) A2(-2.543,3.958) A3(-1.273,3.958) A4(-0.003,3.958) A5(1.267,3.958) A6(2.537,3.958) A7(3.807,3.958) B1(-3.813,2.688) B2(-2.543,2.688) B3(-1.273,2.688) B4(-0.003,2.688) B5(1.267,2.688) B6(2.537,2.688) B7(3.807,2.688) E1(-3.813,-1.122) E2(-2.543,-1.122) E3(-1.273,-1.122) E4(-0.003,-1.122) E5(1.267,-1.122) E6(2.537,-1.122) E7(3.807,-1.122) F3(-1.273,-2.392) F4(-0.003,-2.392) F5(1.267,-2.392) F6(2.537,-2.392) F7(3.807,-2.392) G1(-3.813,-3.662) G2(-2.543,-3.662) G4(-0.003,-3.662) G5(1.267,-3.662) G6(2.537,-3.662) G7(3.807,-3.662) H1(-3.813,-4.932) H2(-2.543,-4.932) H4(-0.003,-4.932) H5(1.267,-4.932) H6(2.537,-4.932) H7(3.807,-4.932)
  silkscreen extent -4.6,-6.11 4.5,5.24, body extent -4.5,-6.11 4.49,5.14, height 5.13
NA5871-AL [mm]
  round 3.38 smd: 1(-21.475,10.918) 4(-21.475,-2.792) 6(22.485,-11.932) 11(22.485,10.918)
  silkscreen extent -26.69,-16.91 24.76,15.89, body extent -23.74,-16.91 24.76,15.89, height 13.6
PEM [mm]
  round 4 hole 3: 1(0,0)
PS2801C [mm]
  rect 1.65x0.65 smd: 1(-3.178,0.677) 2(-3.178,-0.593) 3(3.222,-0.593) 4(3.222,0.677)
  silkscreen extent -4,-1.31 2.05,1.39, body extent 0.02,0.04 0.02,0.04
R_0402 [mm]
  rect 0.5x0.6 smd: 1(-0.5,0) 2(0.5,0)
  silkscreen extent -1.1,-0.6 1.1,0.6
R_0603 [mm]
  rect 0.6x0.9 smd: 1(-0.75,0) 2(0.75,0)
  silkscreen extent -1.4,-0.8 1.4,0.8
R_0805 [mm]
  rect 0.7x1.3 smd: 1(-0.95,0) 2(0.95,0)
  silkscreen extent -1.7,-1 1.7,1
R_2512 [mm]
  rect 1.6x3.5 smd: 1(-2.6,0) 2(2.6,0)
  silkscreen extent -3.8,-2.1 3.8,2.1
R_SM2W [mm]
  rect 1.5x1.4 smd: 1(-2.6,0) 2(2.6,0)
  silkscreen extent -4.5,-2.5 4.6,2.5
R_WSC2515 [mm]
  rect 3x2.4 smd: 1(-2.75,0) 2(2.75,0)
  silkscreen extent -5.55,-2.5 5.55,2.5
TEST_POINT [mm]
  round 4 hole 1: 1(0,0)
ULT2C150MNL1GS [mil]
  rect 138x59 smd paste+0 mask+0: 1(-130.77,2.44) 2(137.23,2.44)
  silkscreen extent -253,-166 172,171, body extent -181,-162 185,165, height 435
UUJ2C101MNJ1MS [mil]
  rect 252x71 smd paste+0 mask+0: 1(-237.83,0) 2(239.17,0)
  silkscreen extent -423,-346 346,346, body extent -344,-341 345,341, height 888

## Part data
C1 C2 C42 C43 C65 C66 C88 C89 C111 C112: "Radial Can - SMD ALUMINUM ELECTROLYTIC CAPACITOR AFK 100V 220muF ±20% 0.709Dia 18.00mm", Case/Package=Radial, ESR (Equivalent Series Resistance)=150mΩ, Leakage Current=220µA, Manufacturer="Cornell Dubilier", Max Operating Temperature=105°C, Min Operating Temperature=-55°C, Ripple Current=687.75mA, Ripple Current (AC)=917mA, Supplier Part Number=338-2172-1-ND, Tolerance=20%, Voltage Rating=100V
C3 C4 C44 C45 C67 C68 C90 C91 C113 C114: "Multilayer Ceramic Chip Capacitors, Capacitance=47μF, LxWxT: 6.0x7.5x6.4mm", Dielectric Material=Ceramic, Manufacturer=TDK, Manufacturer Lifecycle Status=PRODUCTION, Max Operating Temperature=125°C, Min Operating Temperature=-55°C, Supplier Part Number=445-CAA573X7S2A476M640LHDKR-ND, Tolerance=20%, Voltage Rating=100V
C5 C6 C46 C47 C69 C70 C92 C93 C115 C116: "Ceramic Capacitor, Multilayer, Ceramic, 100V, 10% +Tol, 10% -Tol, X7S, 22% TC, 4.7uF, Surface Mount, 1210", Dielectric Material=Ceramic, Manufacturer="Cal-Chip Electronics", Max Operating Temperature=125°C, Min Operating Temperature=-55°C, Supplier Part Number=4713-GMC32X7S475K100NTCT-ND, Voltage Rating (DC)=100V
C7 C8 C14 C24 C26 C30 C32 C48 C49 C56 C71 C72 C78 C94 C95 C102 C117 C118 C124: "Ceramic Capacitor, Multilayer, Ceramic, 50V, 10% +Tol, 10% -Tol, X7R, 15% TC, 4.7uF, Surface Mount, 1206", Dielectric Material=Ceramic, Manufacturer="Cal-Chip Electronics", Max Operating Temperature=125°C, Min Operating Temperature=-55°C, Supplier Part Number=4713-GMC31X7R475K50NTCT-ND, Voltage Rating (DC)=50V
C9 C10 C39 C50 C51 C73 C74 C96 C97 C119 C120: "Ceramic Capacitor, Multilayer, Ceramic, 50V, 20% +Tol, 20% -Tol, X7R, 15% TC, 47uF, Surface Mount, 2420", Dielectric Material=Ceramic, Manufacturer=TDK, Manufacturer Lifecycle Status=PRODUCTION, Max Operating Temperature=125°C, Min Operating Temperature=-55°C, Supplier Part Number=445-CKG57NX7R1H476M500JJCT-ND, Voltage Rating (DC)=50V
C11 C52 C75 C98 C121: "Aluminum Electrolytic Capacitors 100 F 160 V Radial, SMD 5000 Hrs 105C", Leakage Current=740µA, Manufacturer=Nichicon, Max Operating Temperature=105°C, Min Operating Temperature=-40°C, Ripple Current=380mA, Supplier Part Number=493-UUJ2C101MNJ1MSCT-ND, Voltage Rating (DC)=160V
C12 C53 C76 C99 C122: "Radial Can - SMD ALUMINUM ELECTROLYTIC CAPACITOR ULT 160V 15muF ±20% 0.315Dia 8.00mm", Case/Package=SMD/SMT, Leakage Current=196µA, Manufacturer=Nichicon, Max Operating Temperature=125°C, Min Operating Temperature=-40°C, Ripple Current=45mA, Supplier Part Number=493-6717-1-ND, Tolerance=20%, Voltage=160V
C13 C21 C23 C54 C62 C64 C77 C85 C87 C100 C108 C110 C123 C131 C133: "50V 1uF X7R ±10% 0805 Multilayer Ceramic Capacitors MLCC - SMD/SMT ROHS", Case Code (Imperial)=0805, Case Code (Metric)=2012, Dielectric=X7R, Dielectric Material=Ceramic, Manufacturer="Samsung Electro-Mechanics", Max Operating Temperature=125°C, Min Operating Temperature=-55°C, Supplier Part Number=1276-1029-6-ND, Tolerance=10%, Voltage=50V
C15 C20 C55 C61 C79 C84 C101 C107 C125 C130: "50V 100nF X7R ±10% 0603 Multilayer Ceramic Capacitors MLCC - SMD/SMT ROHS", Case Code (Imperial)=0603, Dielectric=X7R, Dielectric Material=Ceramic, Manufacturer=KEMET, Max Operating Temperature=125°C, Min Operating Temperature=-55°C, Supplier Part Number=399-C0603C104K5RACTUCT-ND, Temperature Coefficient=30ppm/°C, Tolerance=10%, Voltage=50V
C16 C57 C80 C103 C126: "Multilayer Ceramic Capacitor, 0.1 pF, 50 V, ± 0.05pF, C0G (NP0), 0402 [1005 Metric]", Case Code (Imperial)=0402, Case Code (Metric)=1005, Dielectric=C0G, Dielectric Material=Ceramic, Manufacturer=Murata, Manufacturer Lifecycle Status="IN PRODUCTION", Max Operating Temperature=125°C, Min Operating Temperature=-55°C, Supplier Part Number=490-11246-1-ND, Temperature Coefficient=30ppm/°C, Voltage Rating=50V
C17 C58 C81 C104 C127: "50V 3.3nF C0G ±1% 0603 Multilayer Ceramic Capacitors MLCC - SMD/SMT ROHS", Case/Package=0603, Dielectric Material=Ceramic, Manufacturer=Murata, Manufacturer Lifecycle Status="IN PRODUCTION", Max Operating Temperature=125°C, Min Operating Temperature=-55°C, Supplier Part Number=490-GCM1885C1H332FA16DCT-ND, Temperature Coefficient=30ppm/°C, Tolerance=1%, Voltage Rating=50V
C18 C59 C82 C105 C128: "50V 470nF X5R ±10% 0402 Multilayer Ceramic Capacitors MLCC - SMD/SMT ROHS", Case/Package=0402, Dielectric=X5R, Dielectric Material=Ceramic, Manufacturer=Murata, Manufacturer Lifecycle Status="IN PRODUCTION", Max Operating Temperature=85°C, Min Operating Temperature=-55°C, Supplier Part Number=490-16354-1-ND, Tolerance=10%, Voltage Rating=50V
C19 C40 C60 C83 C106 C129: "Capacitor, Multilayer, Ceramic, 50V, 10%, X7R, 15% Tc, 0.01Uf, Surface Mount, 0603", Case Code (Imperial)=0603, Dielectric=X7R, Dielectric Material=Ceramic, Manufacturer=KEMET, Max Operating Temperature=125°C, Min Operating Temperature=-55°C, Supplier Part Number=399-C0603C103K5RACTUCT-ND, Temperature Coefficient=30ppm/°C, Tolerance=10%, Voltage=50V
C22 C63 C86 C109 C132: "Ceramic Capacitor, Multilayer, Ceramic, 50V, 20% +Tol, 20% -Tol, X7R, 15% TC, 22uF, Surface Mount, 2220", Dielectric Material=Ceramic, Manufacturer="Cal-Chip Electronics", Max Operating Temperature=125°C, Min Operating Temperature=-55°C, Supplier Part Number=4713-GMC55X7R226M50NTCT-ND, Voltage Rating (DC)=50V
